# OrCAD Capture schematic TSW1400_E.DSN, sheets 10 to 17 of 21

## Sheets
10 Bank 3: size B; title: Bank3
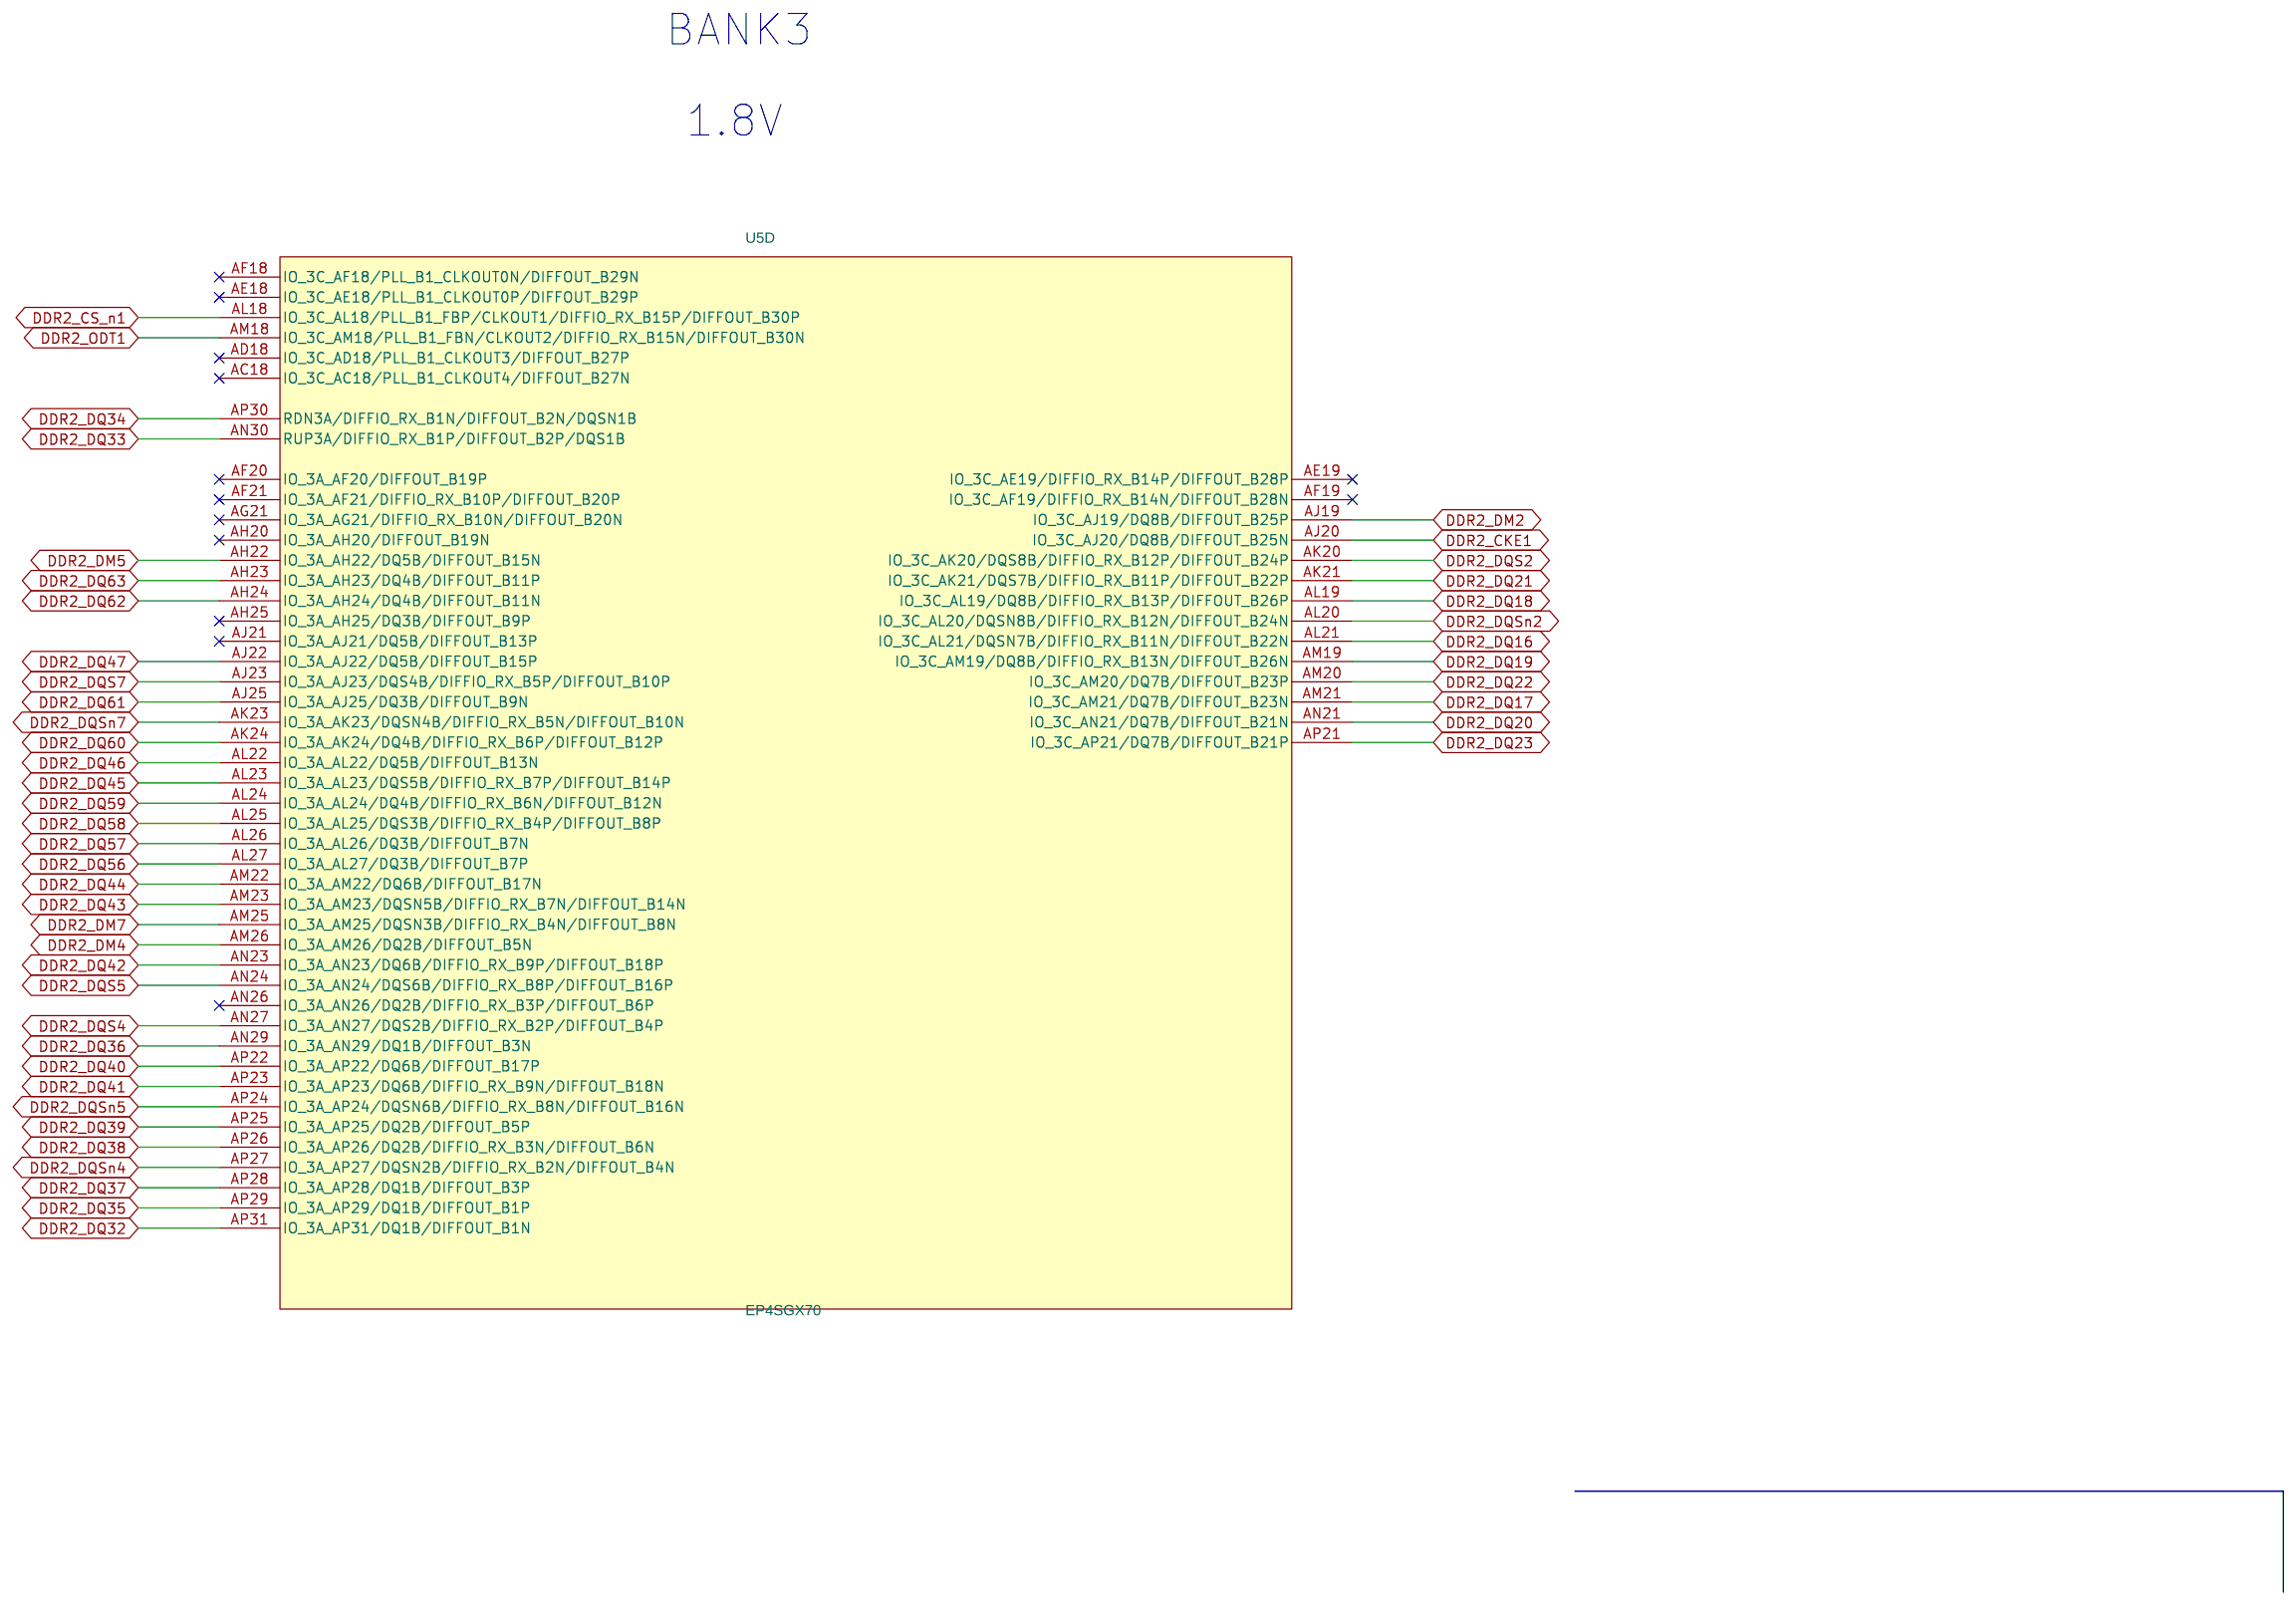
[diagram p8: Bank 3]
11 Bank4: size B; title: Bank4
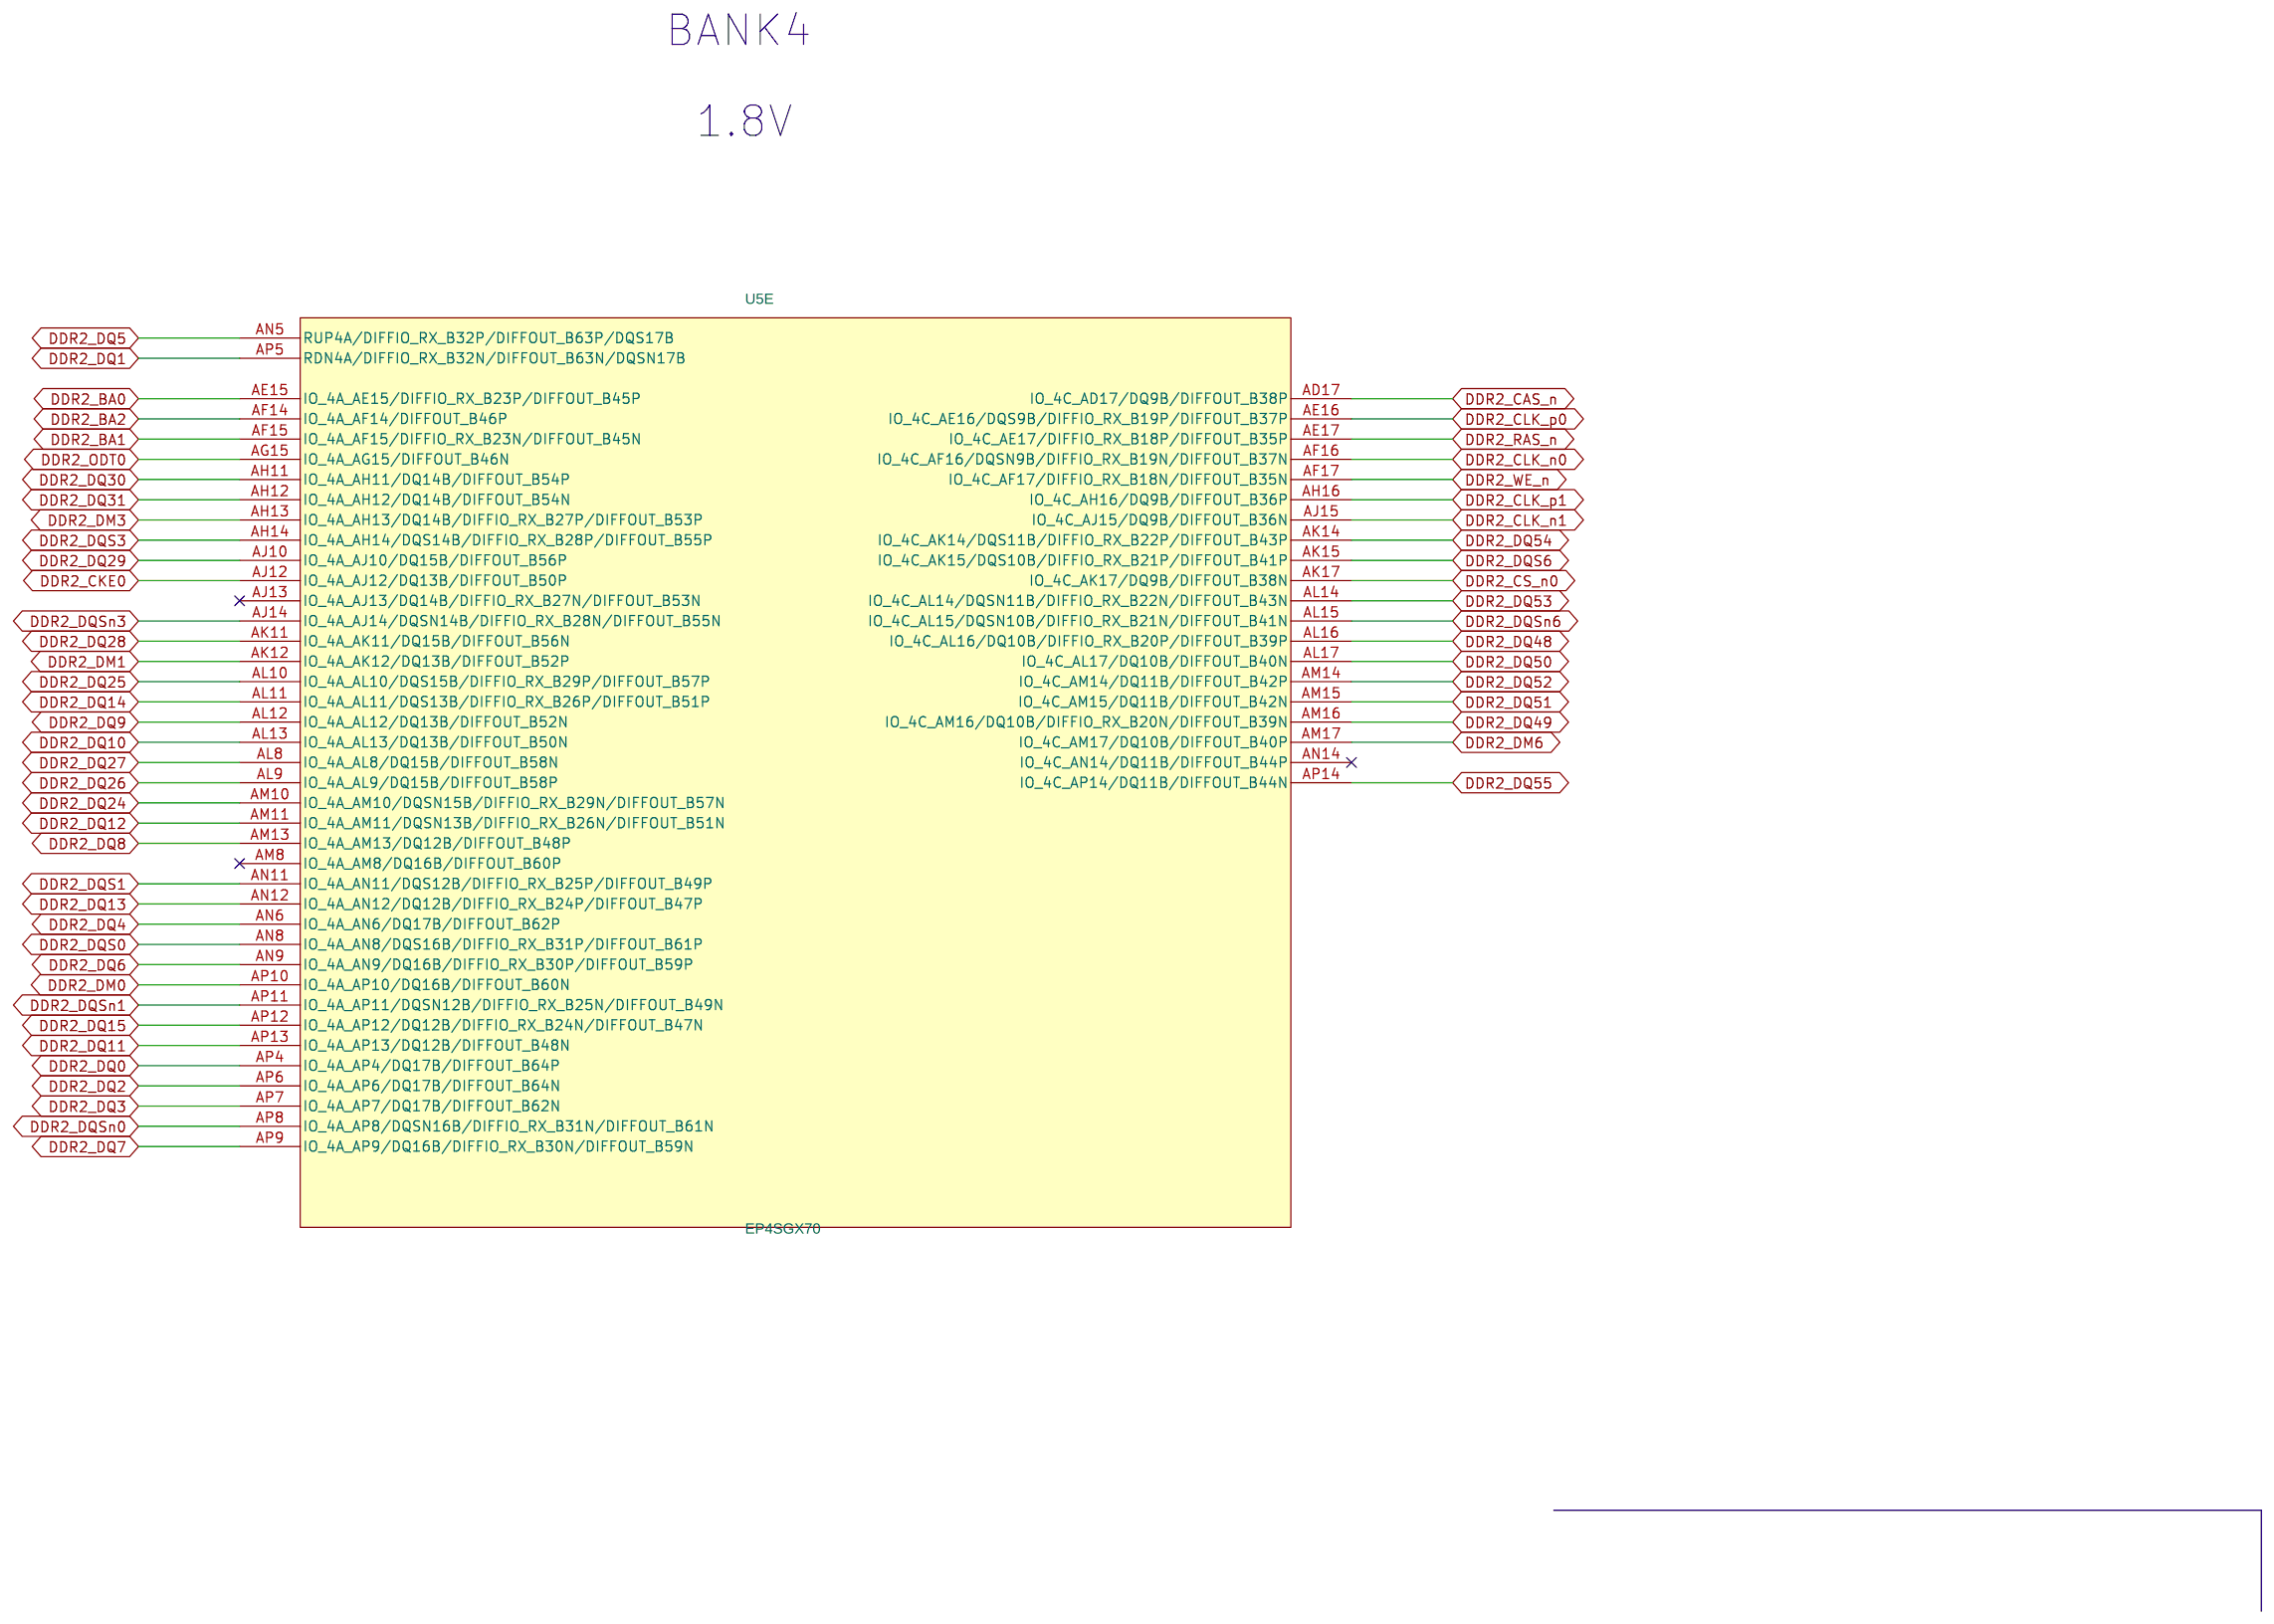
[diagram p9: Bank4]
12 Bank5: size B; title: Bank5
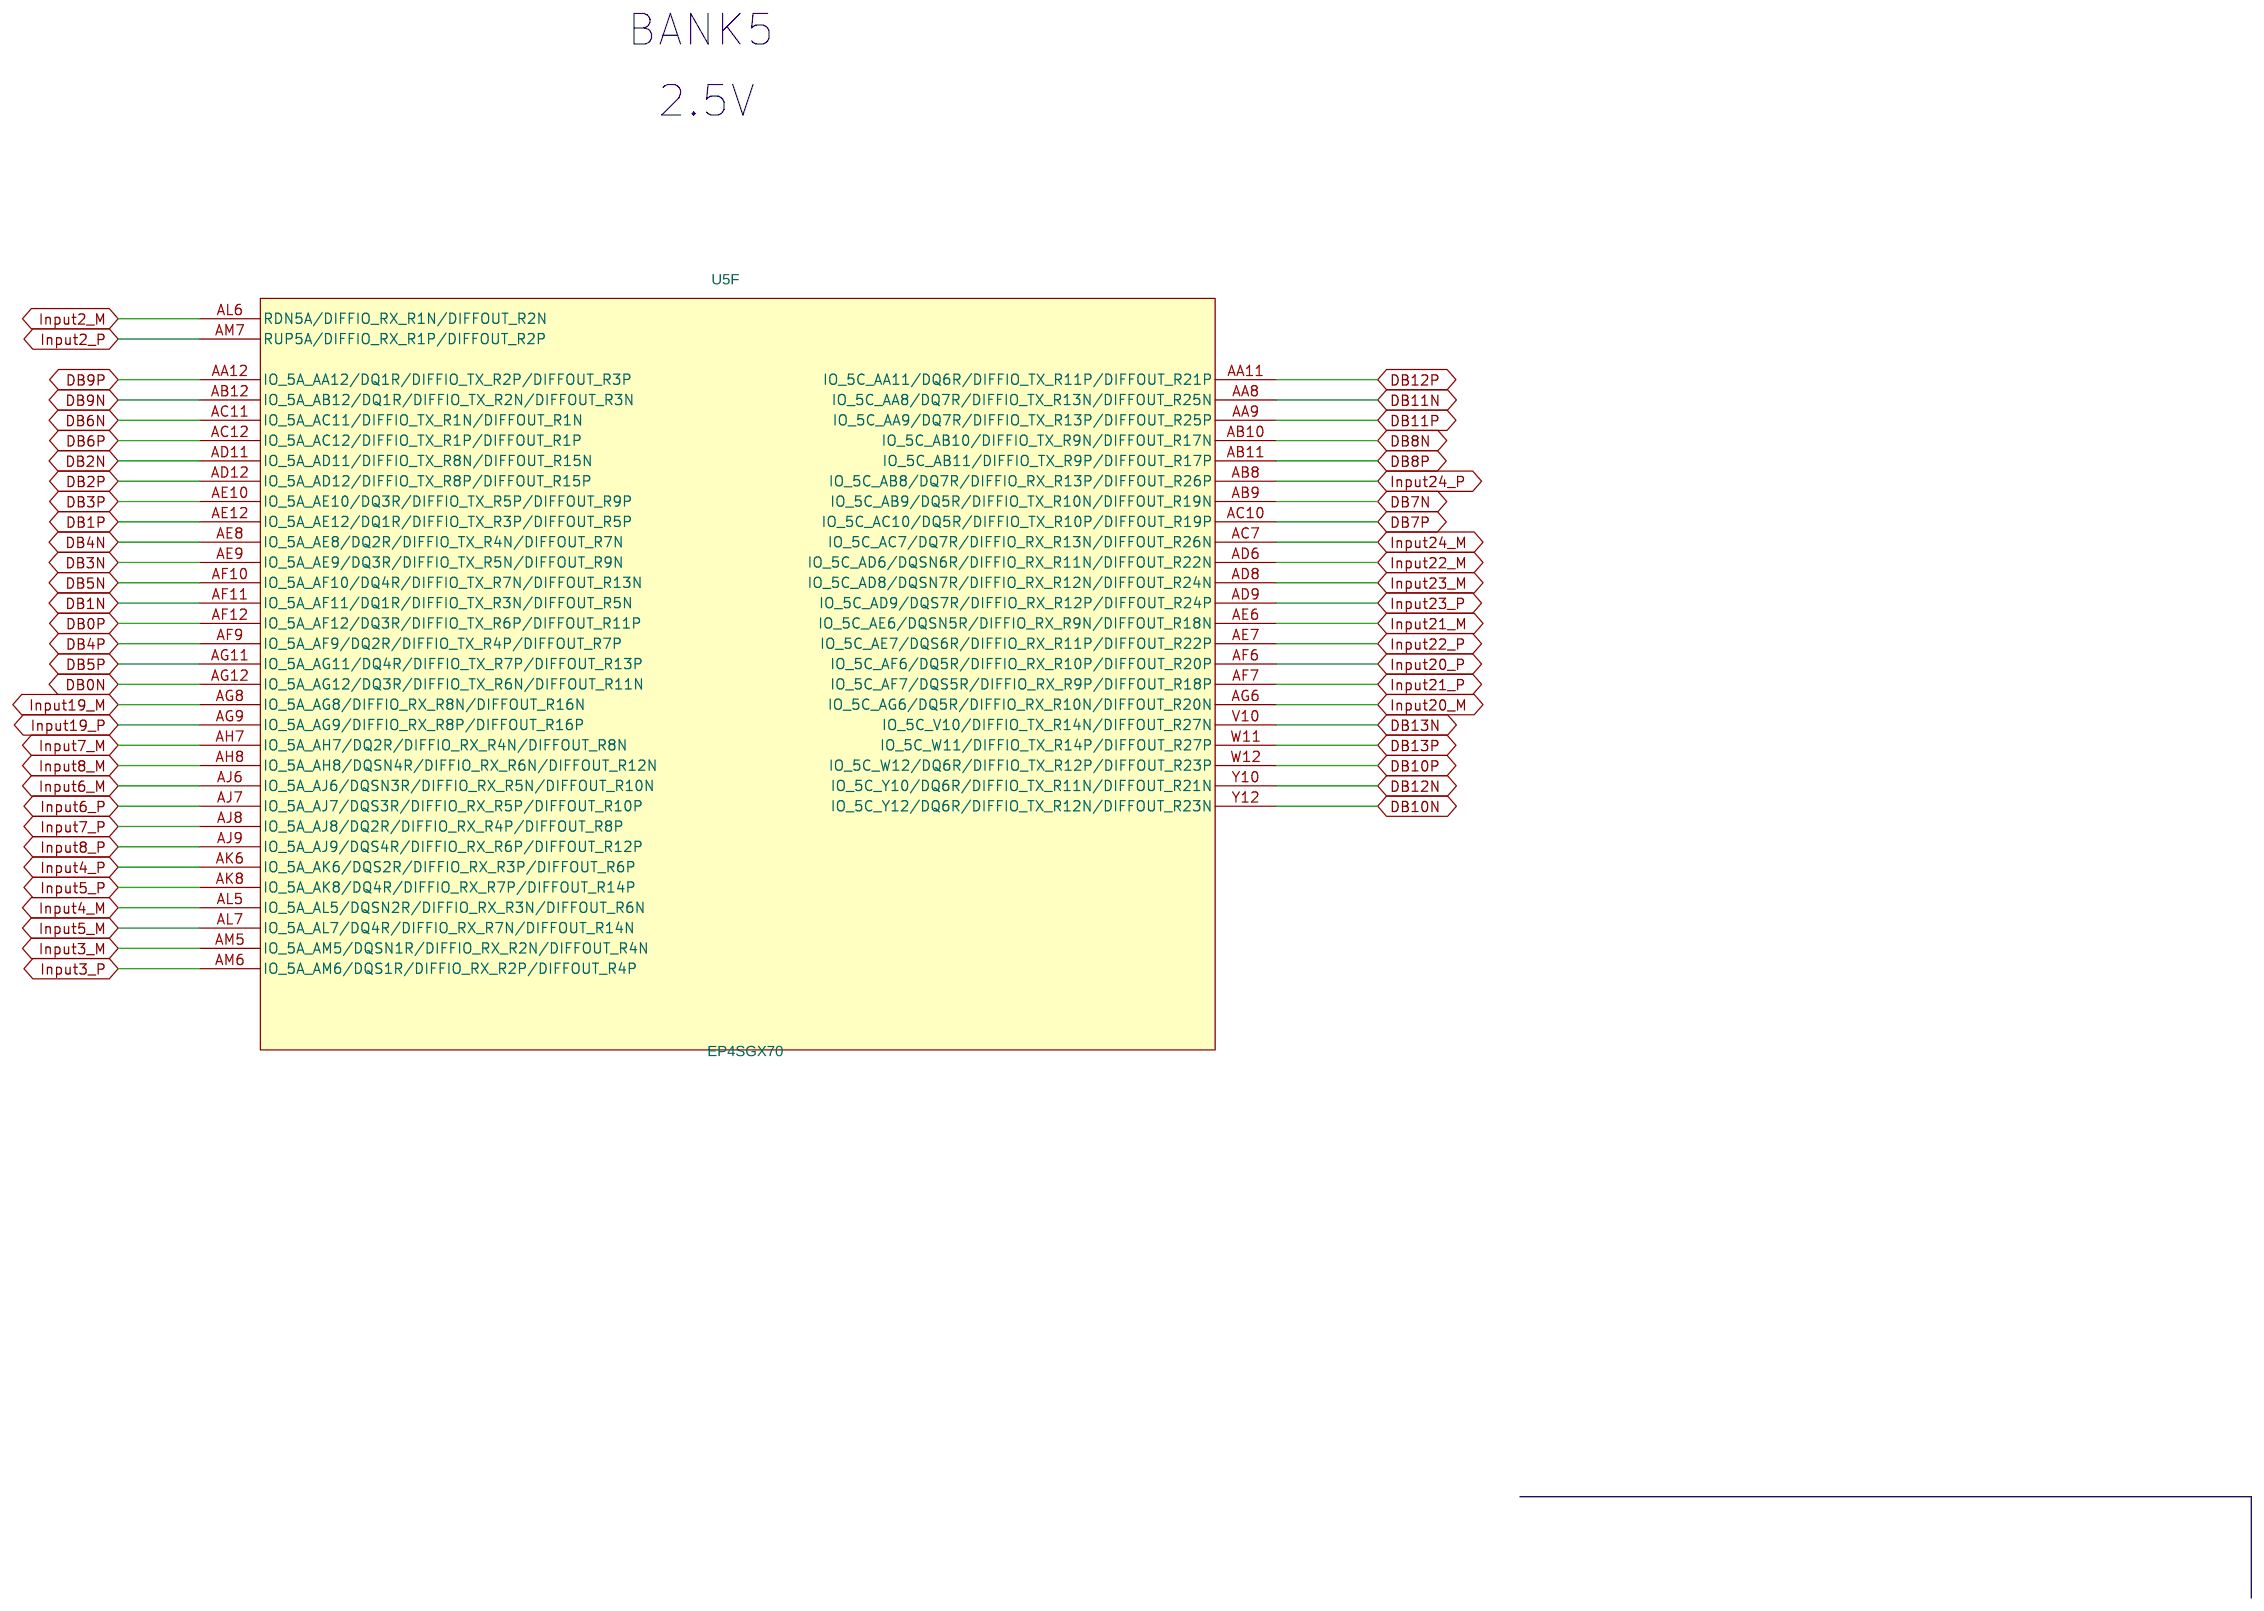
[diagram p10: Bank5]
13 Bank6: size B; title: Bank6
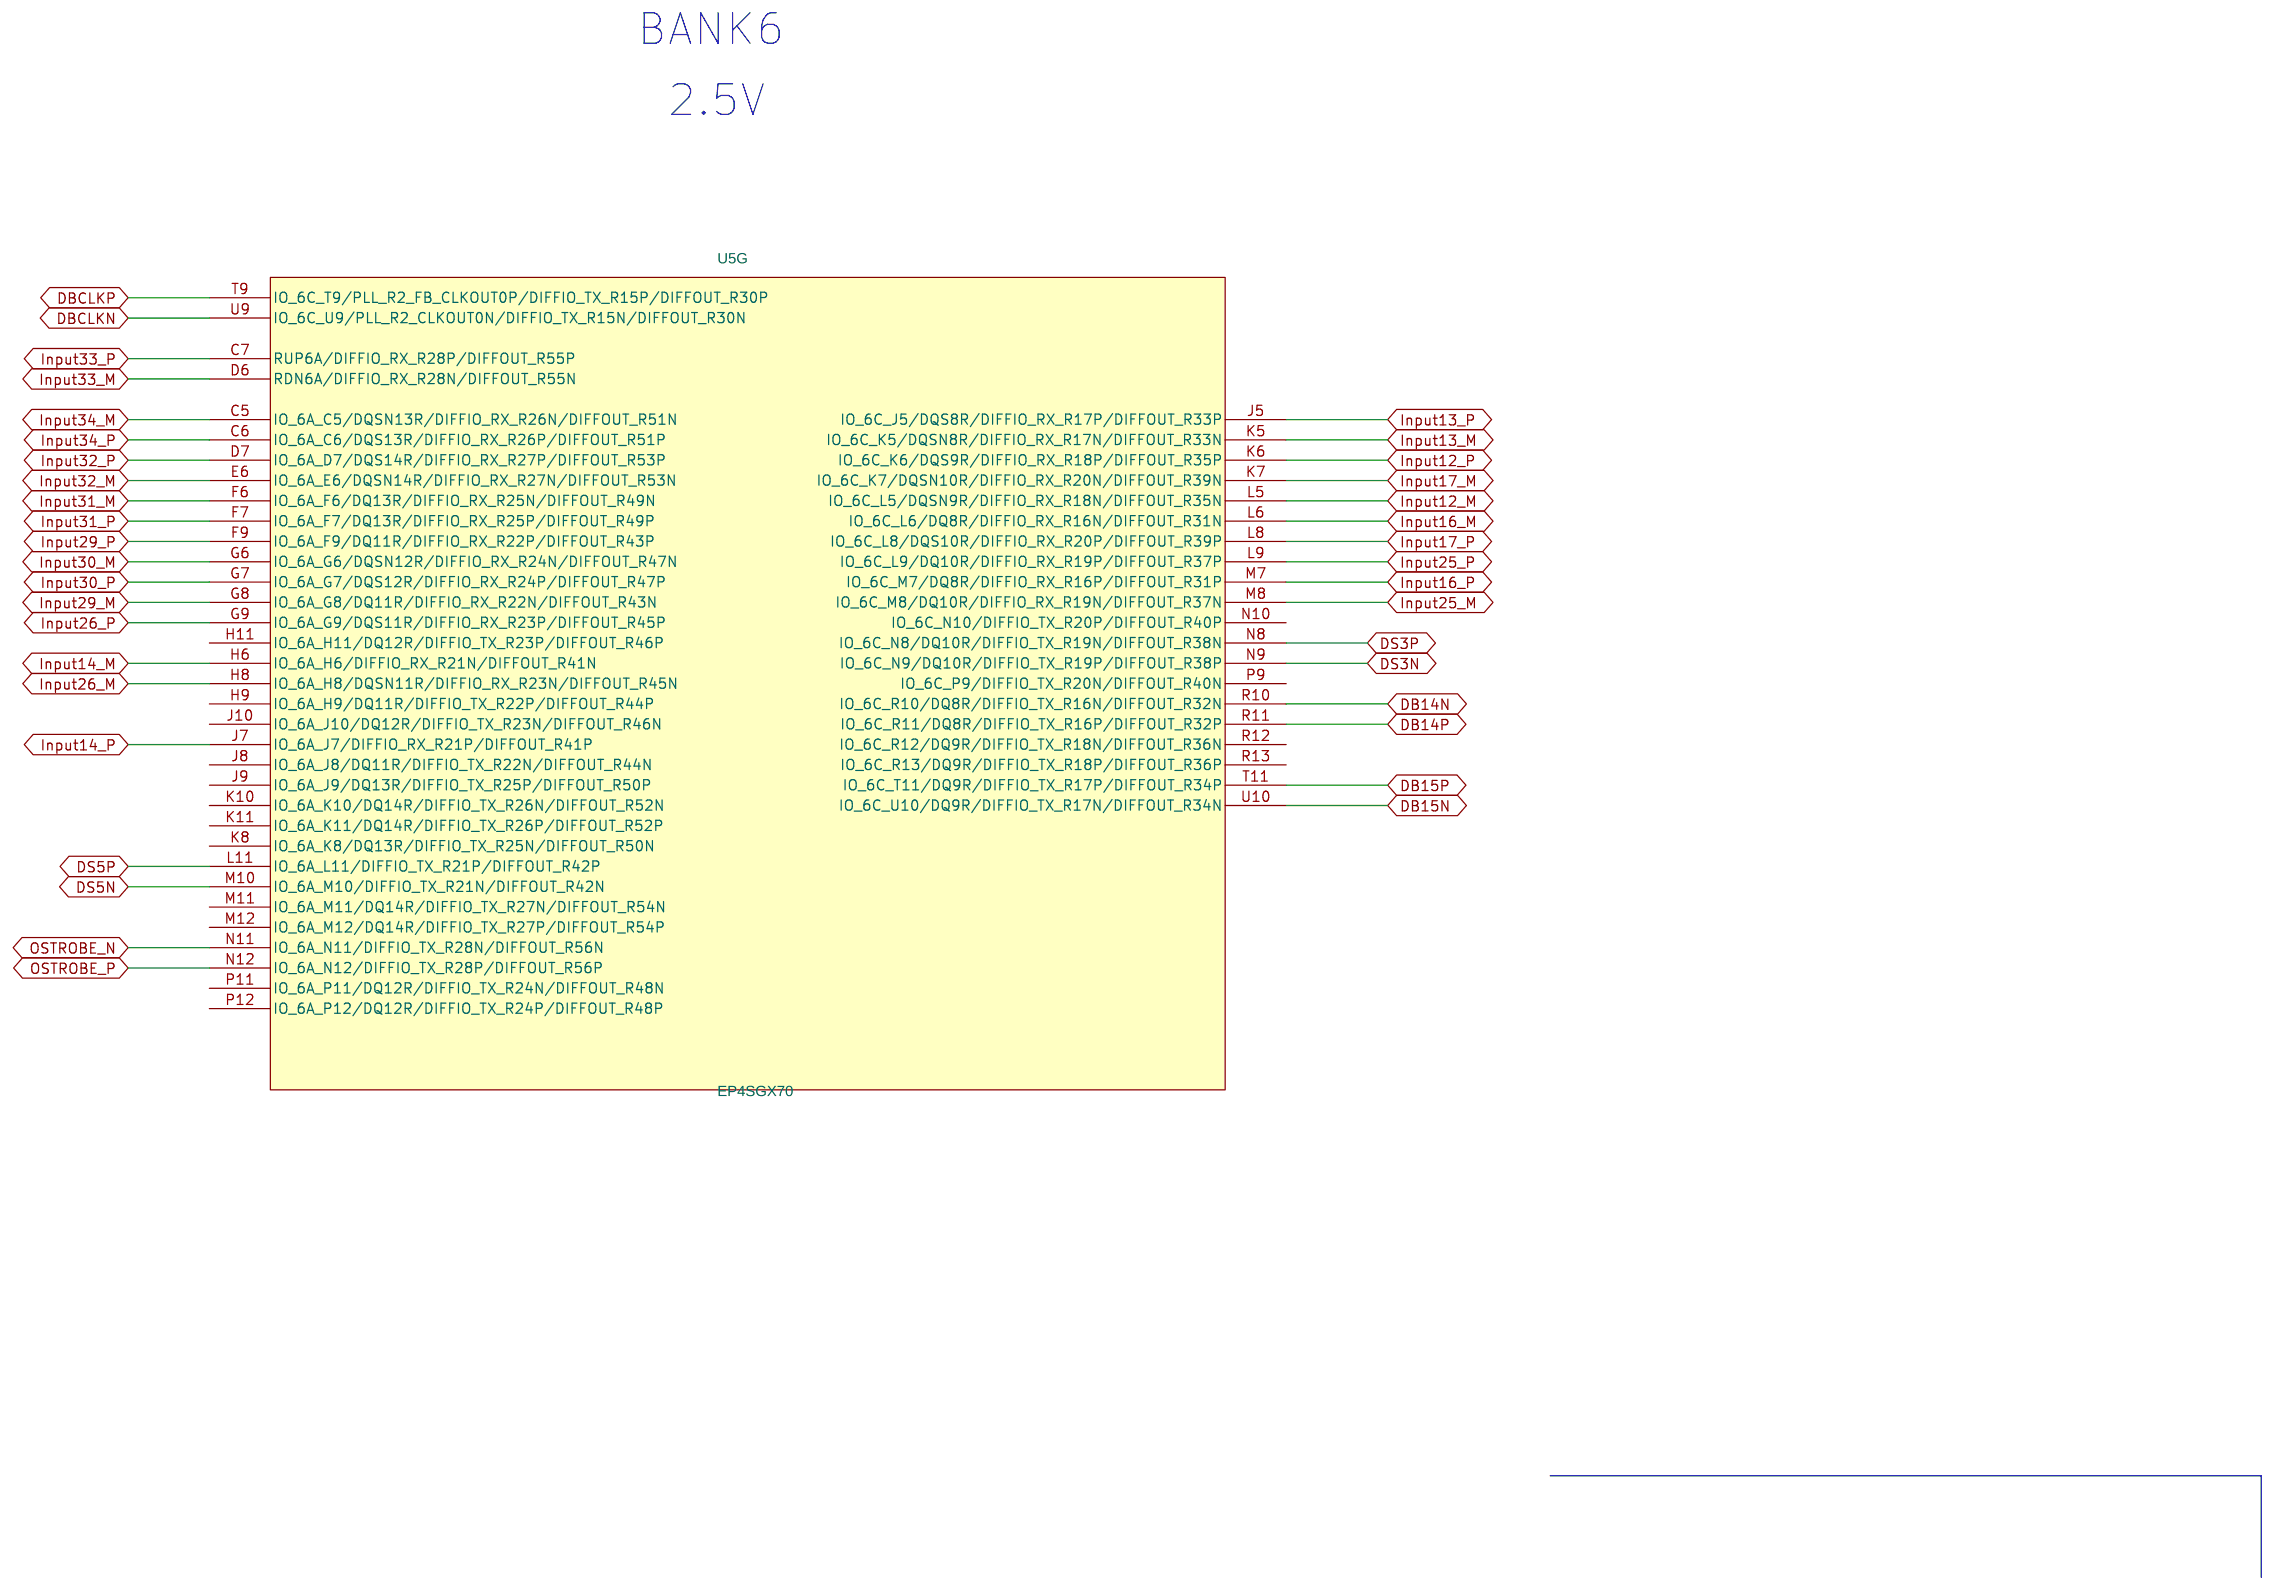
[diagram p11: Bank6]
14 Bank7: size B; title: Bank7
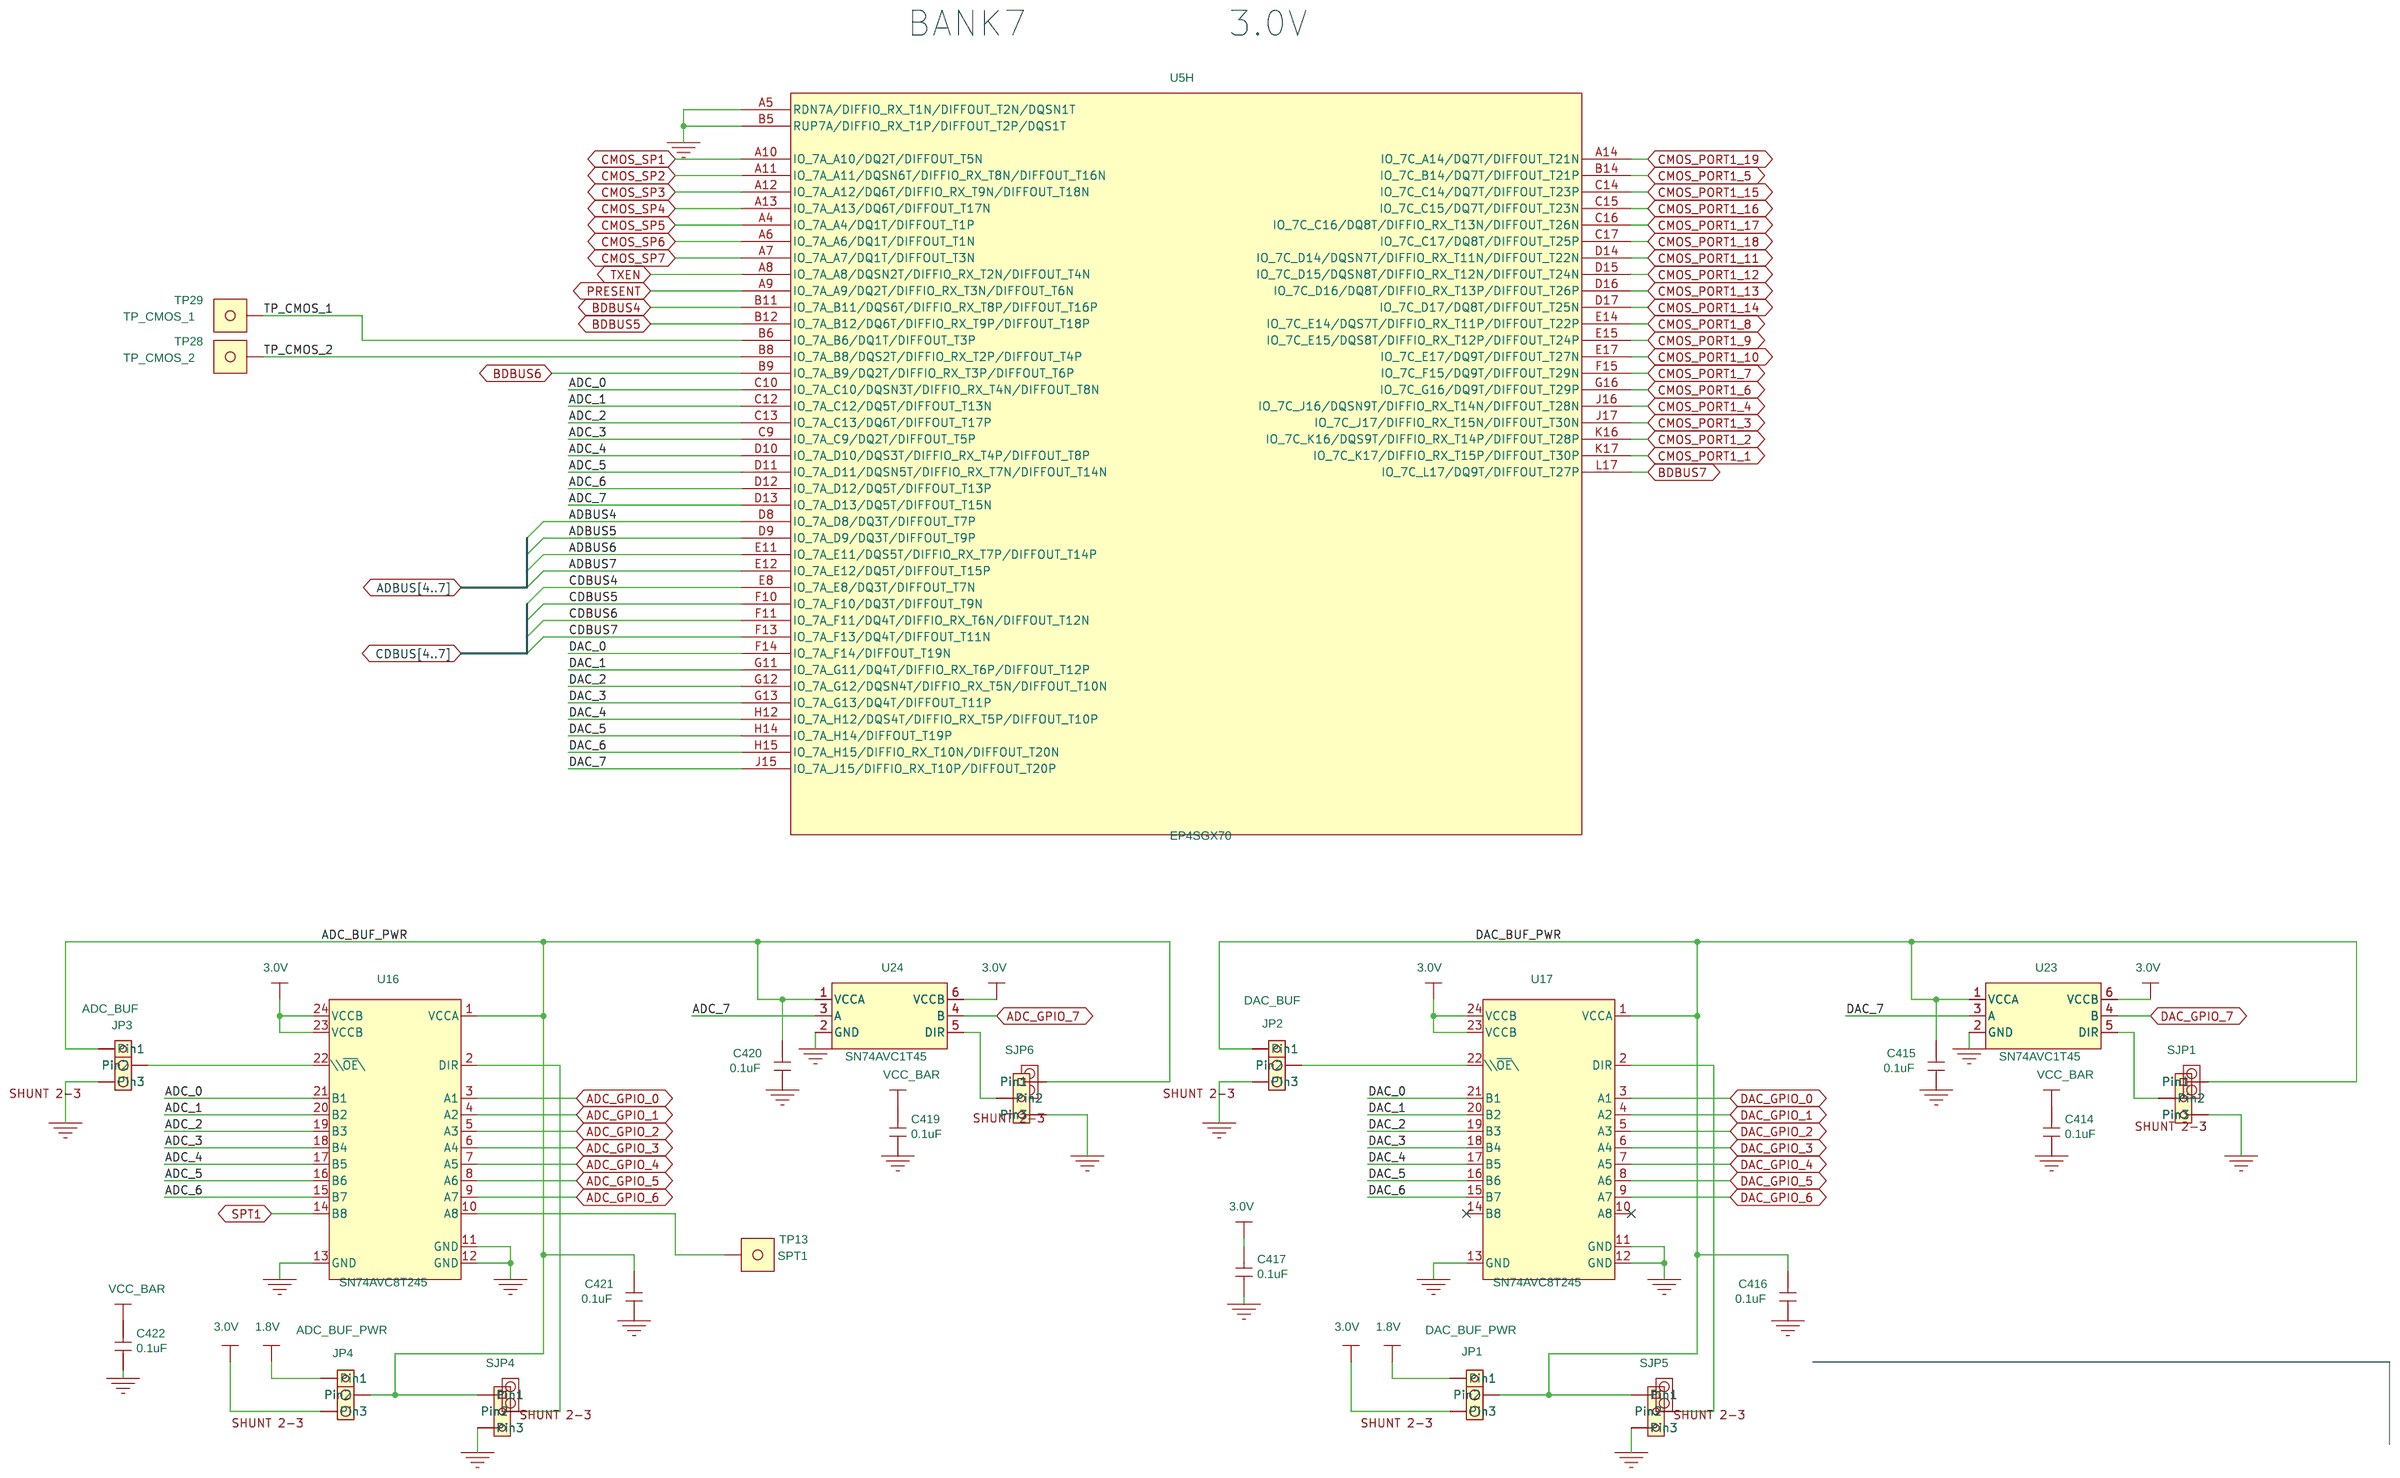
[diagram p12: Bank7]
15 Bank8: size B; title: Bank8
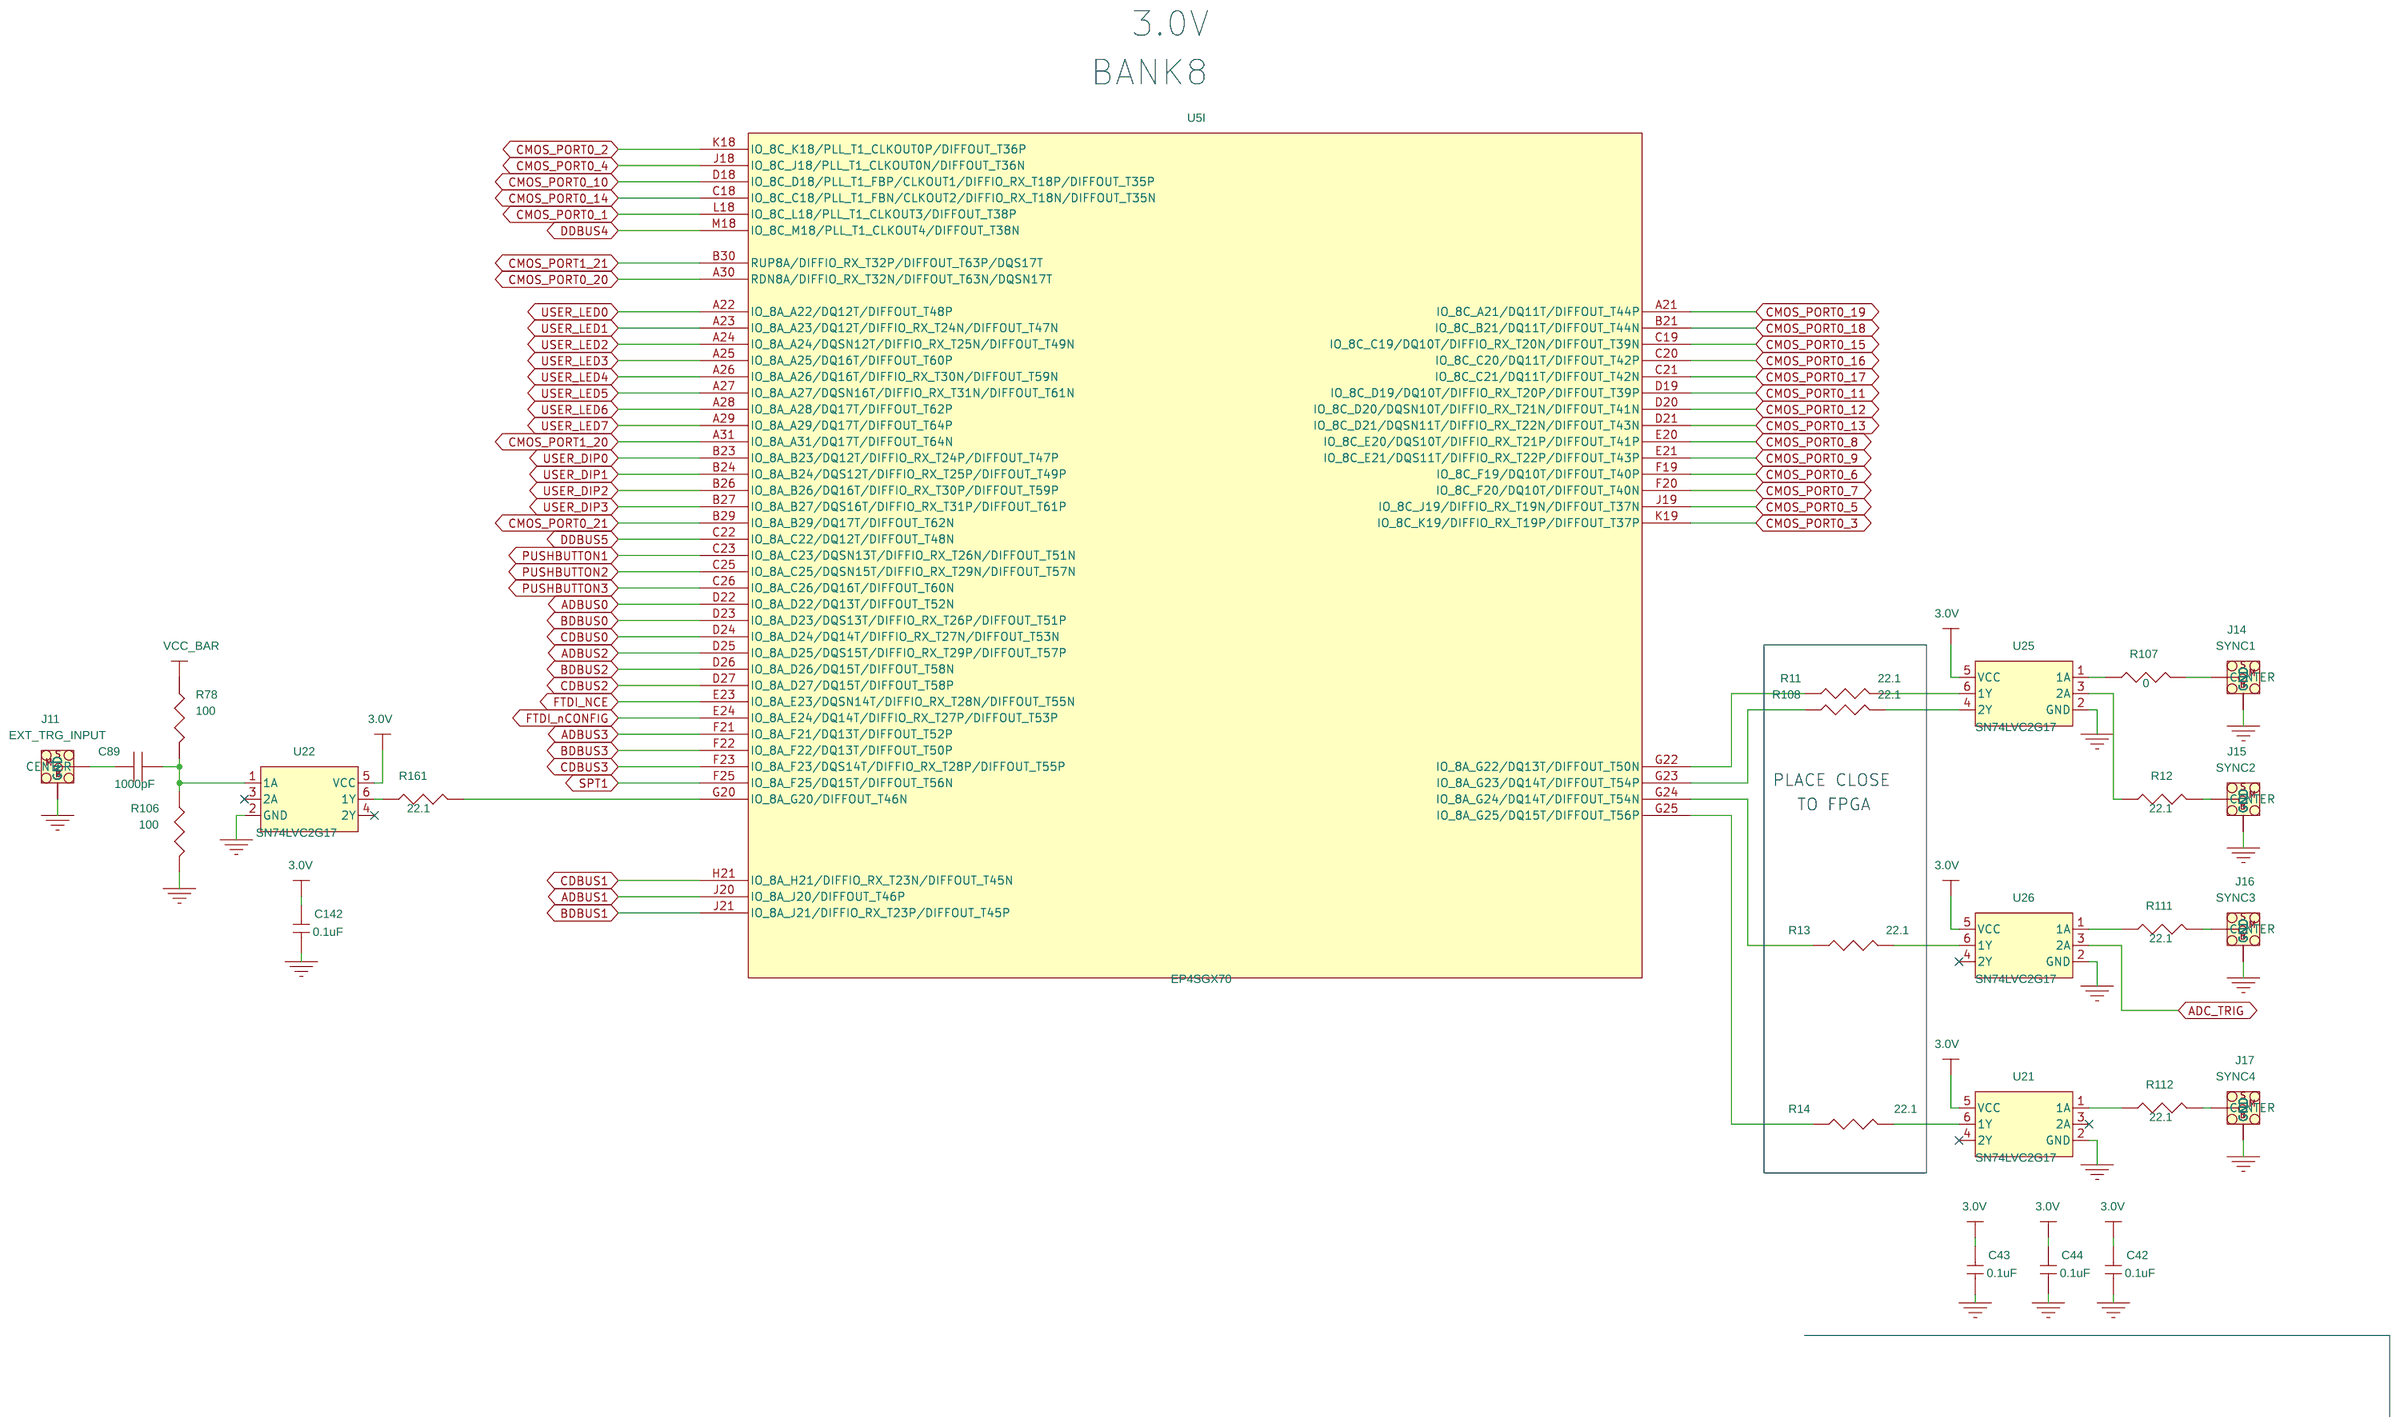
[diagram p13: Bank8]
16 FPGA 0.9V, 1.1V, 1.5V, 1.8: size B; title: POWERS 0.9V, 1.1V, 1.5V, 1.8V
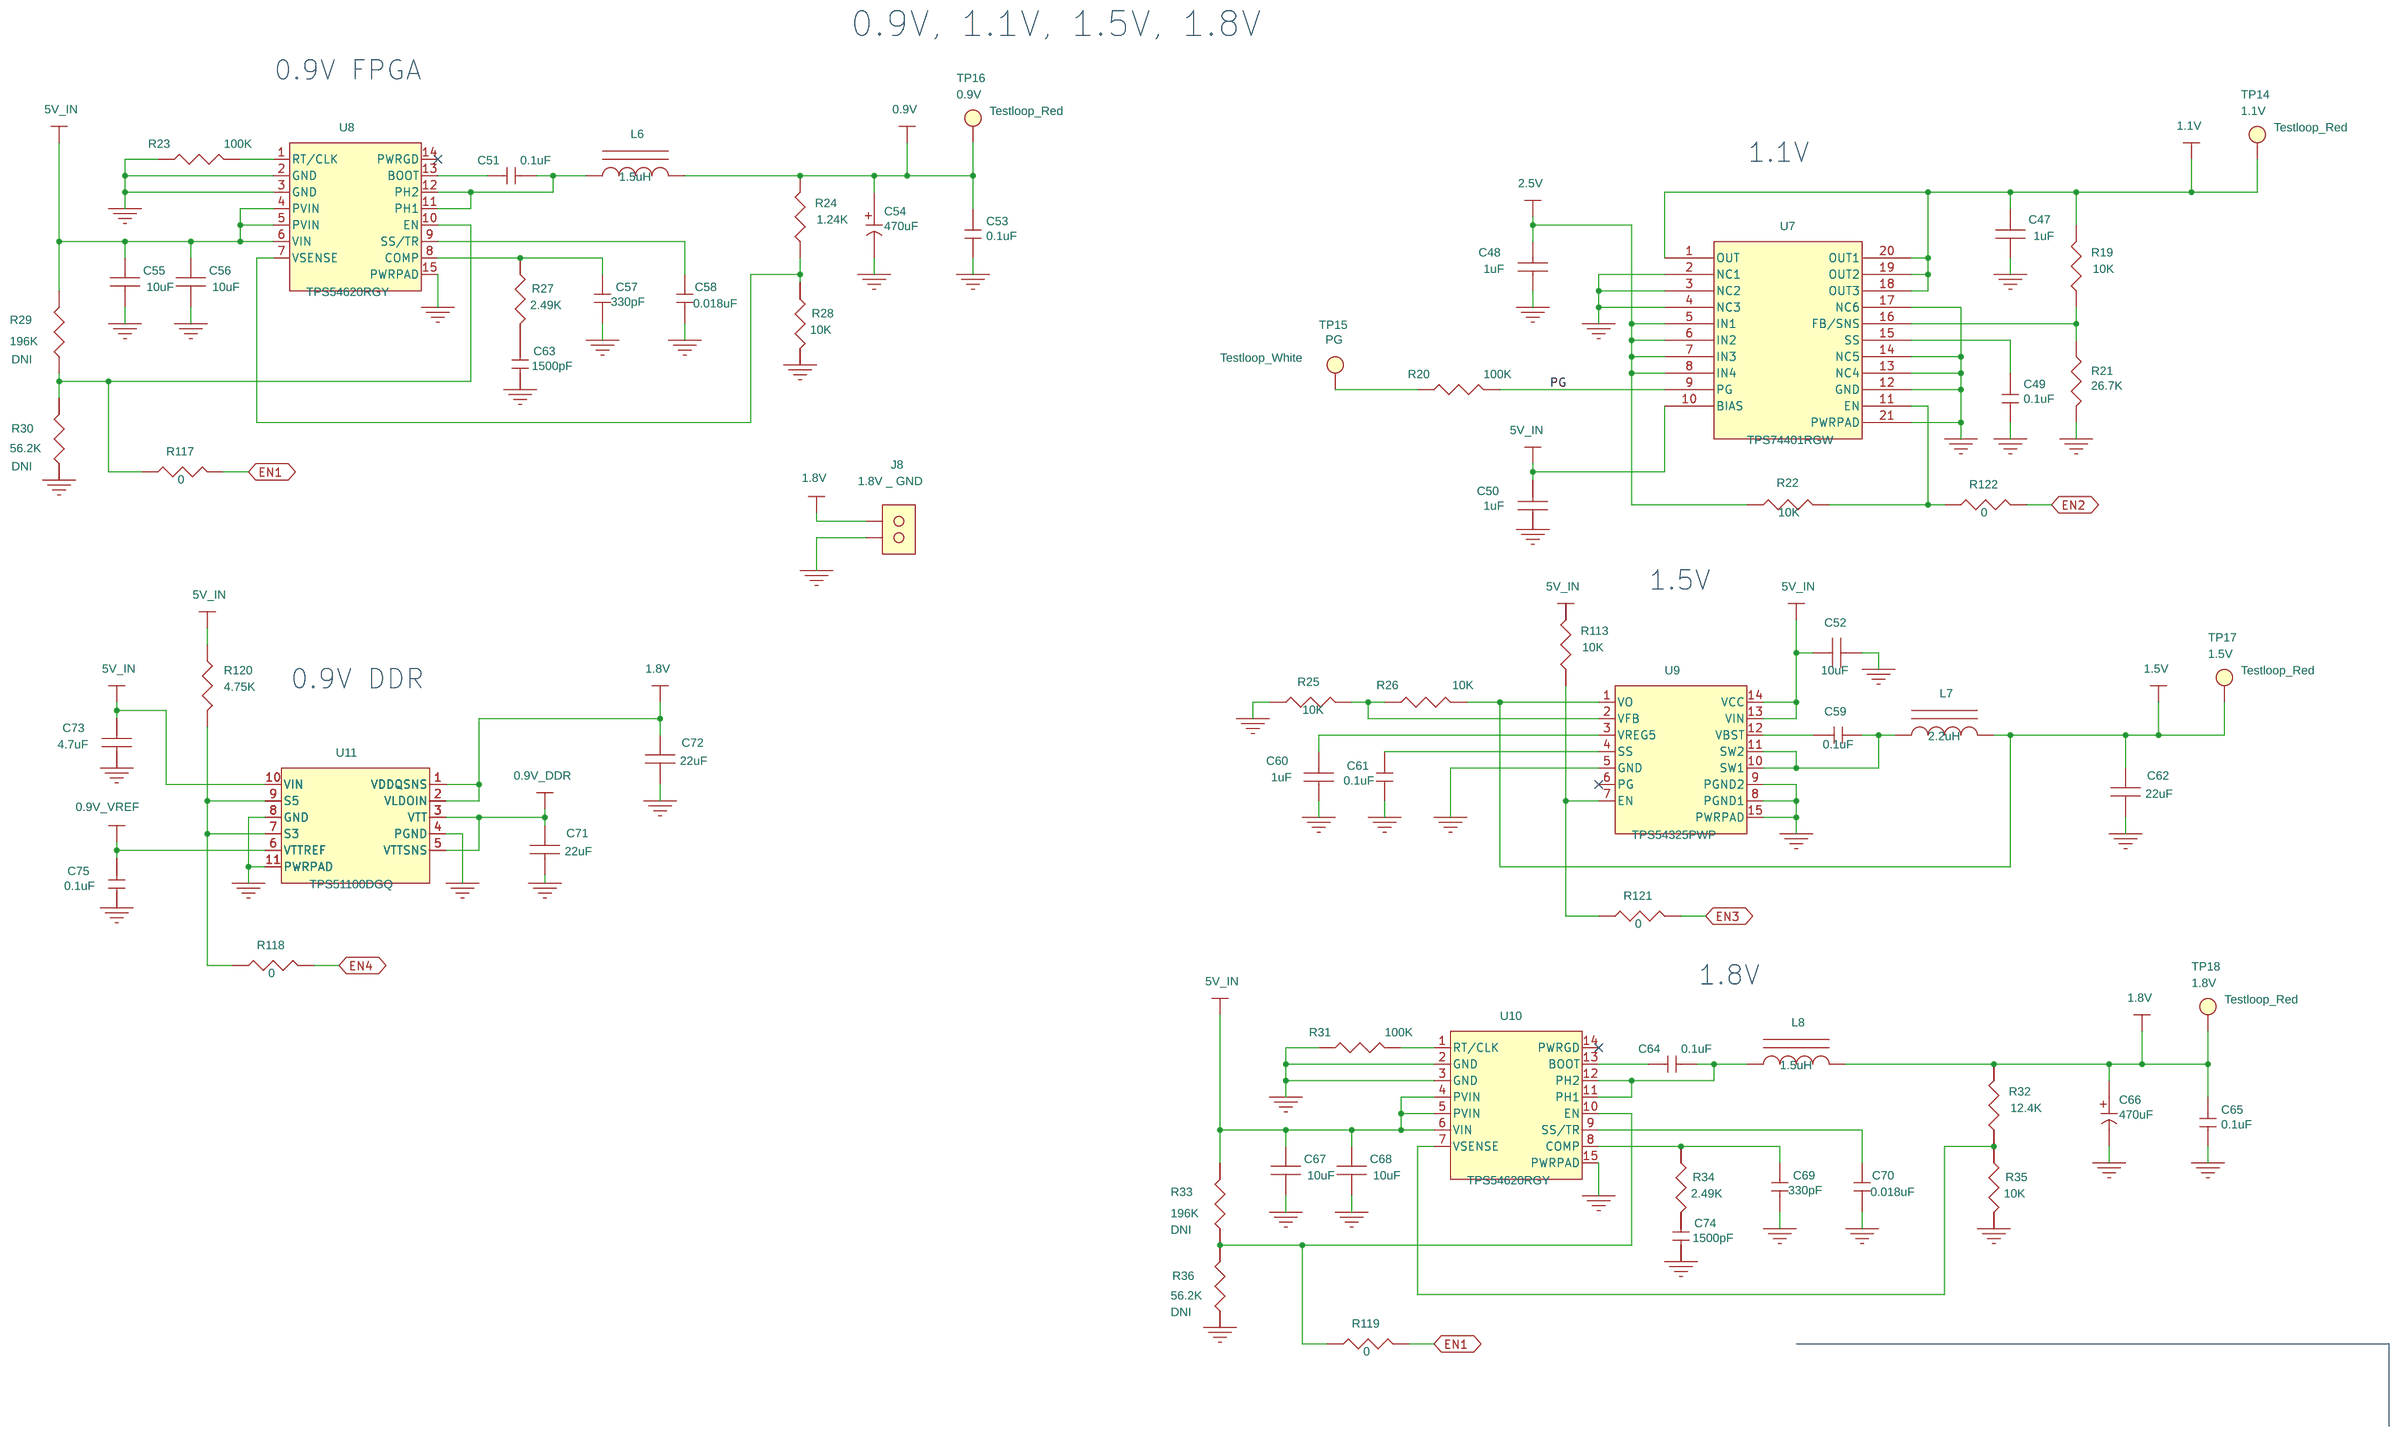
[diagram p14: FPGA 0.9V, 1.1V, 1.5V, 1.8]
17 FPGA 2.5V, 3.0V, 3.3V, 5V: size B; title: POWERS 2.5V, 3.0V, 3.3V, 5V
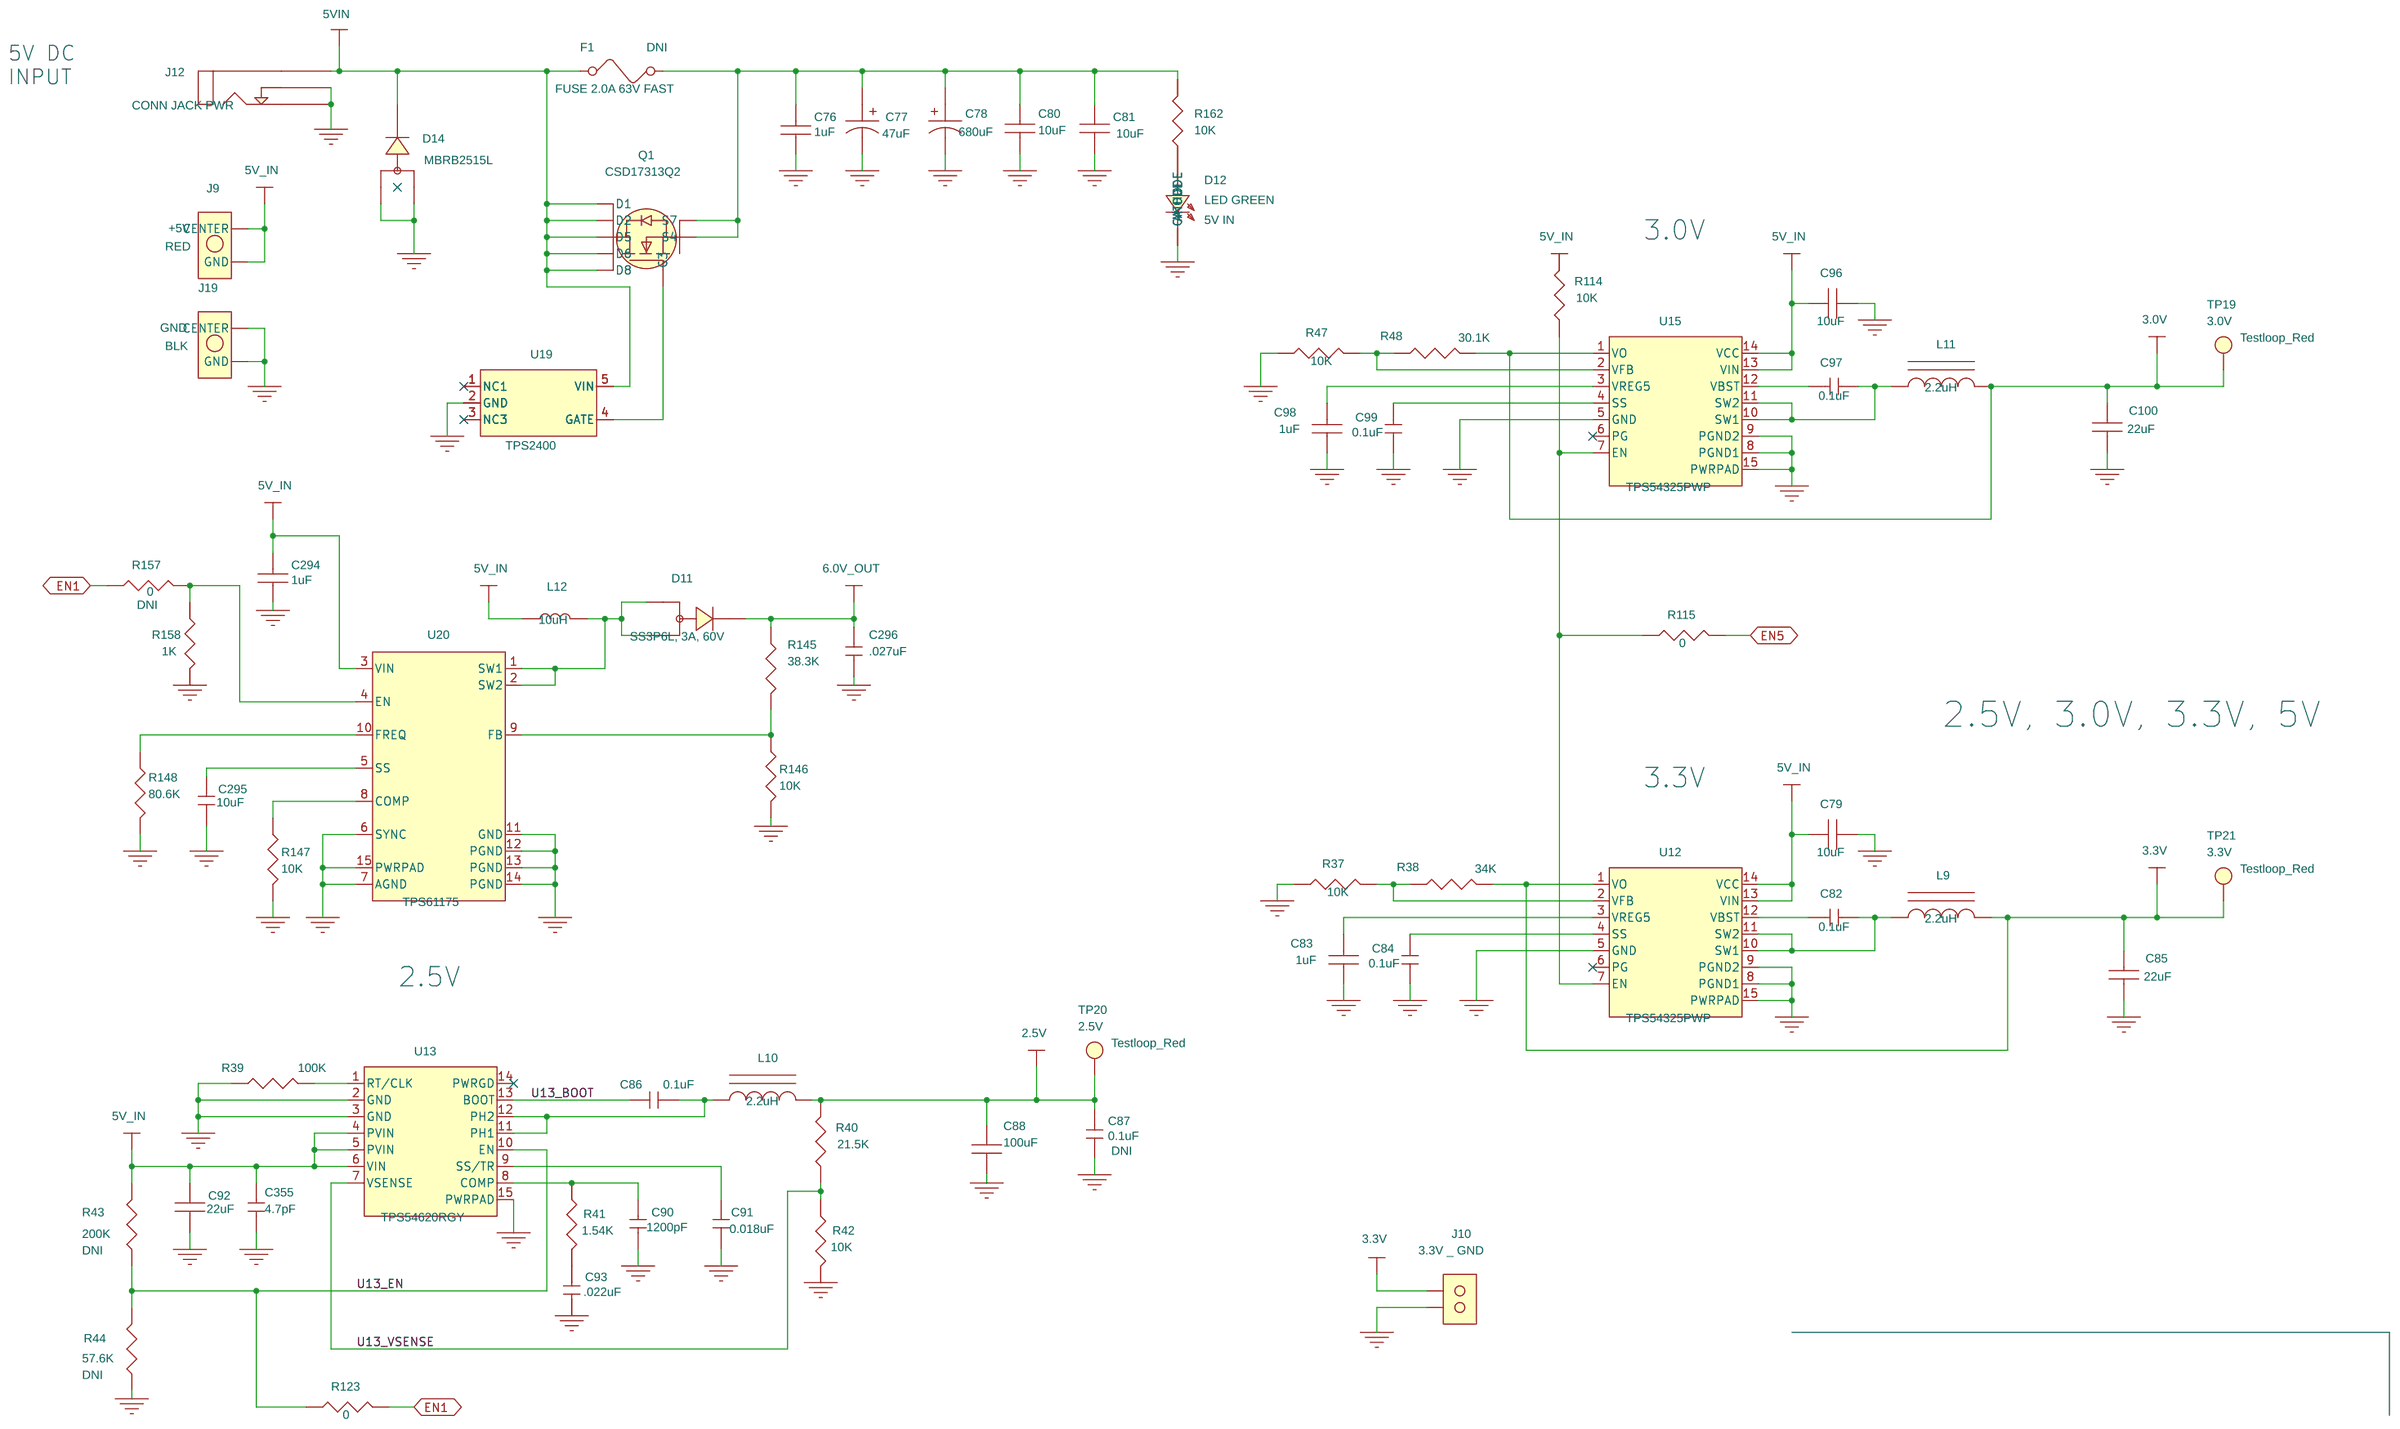
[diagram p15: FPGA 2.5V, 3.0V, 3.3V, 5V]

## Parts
sheet Bank7
C414  0.1uF  [0402]
C415  0.1uF  [0402]
C416  0.1uF  [0402]
C417  0.1uF  [0402]
C419  0.1uF  [0402]
C420  0.1uF  [0402]
C421  0.1uF  [0402]
C422  0.1uF  [0402]
JP1  HDR, THVT, 2POS  [HDR_THVT_1x3_100_M]
JP2  HDR, THVT, 2POS  [HDR_THVT_1x3_100_M]
JP3  HDR, THVT, 2POS  [HDR_THVT_1x3_100_M]
JP4  HDR, THVT, 2POS  [HDR_THVT_1x3_100_M]
SJP1  SOLDER JUMPER, 0603  [JUMPER_SMT_L_0603]
SJP4  SOLDER JUMPER, 0603  [JUMPER_SMT_L_0603]
SJP5  SOLDER JUMPER, 0603  [JUMPER_SMT_L_0603]
SJP6  SOLDER JUMPER, 0603  [JUMPER_SMT_L_0603]
TP13  HDR, THVT, 1POS  [HDR_THVT_1x1]
TP28  HDR, THVT, 1POS  [HDR_THVT_1x1]
TP29  HDR, THVT, 1POS  [HDR_THVT_1x1]
U16  SN74AVC8T245  [TVSOP_24_201X177_16]
U17  SN74AVC8T245  [TVSOP_24_201X177_16]
U23  SN74AVC1T45  [SOT_6_120X69_37]
U24  SN74AVC1T45  [SOT_6_120X69_37]
Z_SH-H37  SHUNT-HEADER
Z_SH-H40  SHUNT-HEADER
Z_SH-H42  SHUNT-HEADER
Z_SH-H43  SHUNT-HEADER
Z_SH-J5  SHUNT-JUMPER-0603
Z_SH-J8  SHUNT-JUMPER-0603
Z_SH-J9  SHUNT-JUMPER-0603
Z_SH-J10  SHUNT-JUMPER-0603
sheet Bank8
C42  0.1uF  [0402]
C43  0.1uF  [0402]
C44  0.1uF  [0402]
C89  1000pF  [0402]
C142  0.1uF  [0402]
J11  SMB_THVT_REC  [SMA_THVT_312x312]
J14  SMB_THVT_REC  [SMA_THVT_312x312]
J15  SMB_THVT_REC  [SMA_THVT_312x312]
J16  SMB_THVT_REC  [SMA_THVT_312x312]
J17  SMB_THVT_REC  [SMA_THVT_312x312]
R11  22.1  [0402]
R12  22.1  [0402]
R13  22.1  [0402]
R14  22.1  [0402]
R78  100  [0402]
R106  100  [0402]
R107  0  [0402]
R108  22.1  [0402]
R111  22.1  [0402]
R112  22.1  [0402]
R161  22.1  [0402]
U21  SN74LVC2G17  [SC70_6_85X55_0P65MM]
U22  SN74LVC2G17  [SC70_6_85X55_0P65MM]
U25  SN74LVC2G17  [SC70_6_85X55_0P65MM]
U26  SN74LVC2G17  [SC70_6_85X55_0P65MM]
sheet Bank 2
U5  EP4SGX70  [BGA_1152_39]  (sections A,B,C,D,E,F,G,H,I,J,K,L,M,N)
sheet FPGA 0.9V, 1.1V, 1.5V, 1.8
C47  1uF  [0603]
C48  1uF  [0603]
C49  0.1uF  [0603]
C50  1uF  [0603]
C51  0.1uF  [0603]
C52  10uF  [0603]
C53  0.1uF  [0603]
C54  470uF  [TANT_E]
C55  10uF  [0603]
C56  10uF  [0603]
C57  330pF  [0603]
C58  0.018uF  [0603]
C59  0.1uF  [0603]
C60  1uF  [0603]
C61  0.1uF  [0603]
C62  22uF  [0603]
C63  1500pF  [0603]
C64  0.1uF  [0603]
C65  0.1uF  [0603]
C66  470uF  [TANT_E]
C67  10uF  [0603]
C68  10uF  [0603]
C69  330pF  [0603]
C70  0.018uF  [0603]
C71  22uF  [0603]
C72  22uF  [0603]
C73  4.7uF  [0603]
C74  1500pF  [0603]
C75  0.1uF  [0603]
J8  HMTSW-102-07-G-S-.240  [HDR_THVT_1x2_100_M]
L6  1.5uH  [IND_SM_MSS1048]
L7  2.2uH  [IND_SM_7447789002]
L8  1.5uH  [IND_SM_MSS1048]
R19  10K  [0603]
R20  100K  [0603]
R21  26.7K  [0603]
R22  10K  [0603]
R23  100K  [0603]
R24  1.24K  [0603]
R25  10K  [0603]
R26  10K  [0603]
R27  2.49K  [0603]
R28  10K  [0603]
R29  196K  [0603]
R30  56.2K  [0603]
R31  100K  [0603]
R32  12.4K  [0603]
R33  196K  [0603]
R34  2.49K  [0603]
R35  10K  [0603]
R36  56.2K  [0603]
R113  10K  [0603]
R117  0  [0603]
R118  0  [0603]
R119  0  [0603]
R120  4.75K  [0603]
R121  0  [0603]
R122  0  [0603]
TP14  Testloop_Red  [TP_THVT_060_RND]
TP15  Testloop_White  [TP_THVT_060_RND]
TP16  Testloop_Red  [TP_THVT_060_RND]
TP17  Testloop_Red  [TP_THVT_060_RND]
TP18  Testloop_Red  [TP_THVT_060_RND]
U7  TPS74401RGW  [QFN_20_203x203_26_pwrpad]
U8  TPS54620RGY  [QFN_14_144x144_pwrpad]
U9  TPS54325PWP  [HTSSOP_14_201x177_26_pwrpad]
U10  TPS54620RGY  [QFN_14_144x144_pwrpad]
U11  TPS51100DGQ  [SOIC_10_122x122_50_pwrpad]
sheet FPGA 2.5V, 3.0V, 3.3V, 5V
C76  1uF  [0603]
C77  47uF  [CAP_SMD_8MM]
C78  680uF  [CAP_SMD_12_5MM]
C79  10uF  [0603]
C80  10uF  [1210]
C81  10uF  [1210]
C82  0.1uF  [0603]
C83  1uF  [0603]
C84  0.1uF  [0603]
C85  22uF  [0603]
C86  0.1uF  [0603]
C87  0.1uF  [0603]
C88  100uF  [1210]
C90  1200pF  [0603]
C91  0.018uF  [0603]
C92  22uF  [0603]
C93  .022uF  [0603]
C96  10uF  [0603]
C97  0.1uF  [0603]
C98  1uF  [0603]
C99  0.1uF  [0603]
C100  22uF  [0603]
C294  1uF  [0603]
C295  10uF  [0603]
C296  .027uF  [0603]
C355  4.7pF  [0603]
D11  SS3P6L, 3A, 60V  [DIODE_SM_SS3P6L]
D12  LED GREEN  [LED_1206]
D14  MBRB2515L  [DIODE_MBRB2515L]
F1  FUSE 2.0A 63V FAST  [1206]
J9  RED  [JACK_THRT_BANANA_2PIN]
J10  HMTSW-102-07-G-S-.240  [HDR_THVT_1x2_100_M]
J12  CONN JACK PWR  [CON_RAPC722_JACK_THVT_3]
J19  BLK  [JACK_THRT_BANANA_2PIN]
L9  2.2uH  [IND_SM_7447789002]
L10  2.2uH  [IND_SM_7447789002]
L11  2.2uH  [IND_SM_7447789002]
L12  10uH  [IND_SM_MSS1048]
Q1  CSD17313Q2  [mosfet_8_2mmx2mm_0p65]
R37  10K  [0603]
R38  34K  [0603]
R39  100K  [0603]
R40  21.5K  [0603]
R41  1.54K  [0603]
R42  10K  [0603]
R43  200K  [0603]
R44  57.6K  [0603]
R47  10K  [0603]
R48  30.1K  [0603]
R114  10K  [0603]
R115  0  [0603]
R123  0  [0603]
R145  38.3K  [0603]
R146  10K  [0603]
R147  10K  [0603]
R148  80.6K  [0603]
R157  0  [0603]
R158  1K  [0402]
R162  10K  [0603]
TP19  Testloop_Red  [TP_THVT_060_RND]
TP20  Testloop_Red  [TP_THVT_060_RND]
TP21  Testloop_Red  [TP_THVT_060_RND]
U12  TPS54325PWP  [HTSSOP_14_201x177_26_pwrpad]
U13  TPS54620RGY  [QFN_14_144x144_pwrpad]
U15  TPS54325PWP  [HTSSOP_14_201x177_26_pwrpad]
U19  TPS2400  [DBV5]
U20  TPS61175  [HTSSOP_14_201X177_26_PWRPAD]

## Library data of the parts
C414-C417 C419-C422 = CAP0603: Mfr_Name: Murata; Mfr_Part_Number: GRM155R71C104KA88D; TOL: 10%; Voltage: 16V
JP1 = JUMPER_1x3_100: Mfr_Name: SAMTEC; Mfr_Part_Number: HTSW-103-07-G-S; TI_Silktext: DAC_BUF_PWR
JP2 = JUMPER_1x3_100: Mfr_Name: SAMTEC; Mfr_Part_Number: HTSW-103-07-G-S; TI_Silktext: DAC_BUF
JP3 = JUMPER_1x3_100: Mfr_Name: SAMTEC; Mfr_Part_Number: HTSW-103-07-G-S; TI_Silktext: ADC_BUF
JP4 = JUMPER_1x3_100: Mfr_Name: SAMTEC; Mfr_Part_Number: HTSW-103-07-G-S; TI_Silktext: ADC_BUF_PWR
SJP1 = Jumper_1x3_100_0: Mfr_Name: NO PART; Mfr_Part_Number: DNI; Shunt: SHUNT 2-3; TI_Silktext: <TI_Silktext>
SJP4 SJP5 = JUMPER_SMD_1X3: Mfr_Name: NO PART; Shunt: SHUNT 2-3; TI_Silktext: <TI_Silktext>
SJP6 = Jumper_1x3_100_0: Manufacturer: NO PART; Mfr_Name: NO PART; Mfr_Part_Number: DNI; Shunt: SHUNT 2-3; TI_Silktext: <TI_Silktext>
TP13 = HEADER_1x1: Mfr_Name: SAMTEC; Mfr_Part_Number: HTSW-101-07-G-S; TI_SILKTEXT: SPT1
TP28 = HEADER_1x1: Mfr_Name: SAMTEC; Mfr_Part_Number: HTSW-101-07-G-S; TI_SILKTEXT: TP_CMOS_2
TP29 = HEADER_1x1: Mfr_Name: SAMTEC; Mfr_Part_Number: HTSW-101-07-G-S; TI_SILKTEXT: TP_CMOS_1
U16 U17 = SN74AVC8T245
U23 U24 = SN74AVC1T45: Mfr_Name: Texas Instruments; Mfr_Part_Number: SN74AVC1T45DBVR
Z_SH-H37 Z_SH-H40 Z_SH-H42 Z_SH-H43 = SHUNT-3PINHEADER: TI_SILK: SHUNT 2-3
Z_SH-J5 Z_SH-J8-Z_SH-J10 = SHUNT-JUMPER-0603: Mfr_Name: PANASONIC; Shunt: SHUNT 2-3
C42-C44 C142 = CAP_0402_0.1uF: Mfr_Name: Murata
C89 = CAP_NP_0: Mfr_Name: TAIYO YUDEN; Mfr_Part_Number: TMK105SD102JV-F; TOL: 5%; VOLTAGE: 25V
J11 = SMA-THVT_142-0701-201_REC: TI_Silktext: EXT_TRG_INPUT
J14 = SMA-THVT_142-0701-201_REC: TI_Silktext: SYNC1
J15 = SMA-THVT_142-0701-201_REC: TI_Silktext: SYNC2
J16 = SMA-THVT_142-0701-201_REC: TI_Silktext: SYNC3
J17 = SMA-THVT_142-0701-201_REC: TI_Silktext: SYNC4
R11-R14 R108 R111 R112 R161 = Res_0402_22.1_H
R78 R106 = Res_0402_100
R107 = Res_0402_Zero_H
U21 U22 U25 U26 = SN74LVC2G17
U5 = EP4SGX70F1152_2
C47 C48 C50 C60 C76 C83 C98 C294 = CAP_0603_H: Mfr_Name: Murata; Mfr_Part_Number: GRM188R60J105KA01D; Tolerance: 10%; Voltage: 6.3V
C49 C51 C53 C59 C61 C64 C65 C75 C82 C84 C86 C97 C99 = CAP0603: Mfr_Name: Murata; Mfr_Part_Number: GRM188R71C104KA01D; PART_NUMBER: ECJ-1VB1C104K; TOL: 10%; Voltage: 16V
C52 C55 C56 C67 C68 C79 C96 = CAP: Mfr_Name: Murata; Mfr_Part_Number: GRM188R60J106ME47D; TOL: 20%; VOLTAGE: 6.3V
C54 C66 = CAP_POL-E: Mfr_Name: Kemet; Mfr_Part_Number: B45197A2477K509
C57 C69 = CAP0603: Mfr_Name: Murata; Mfr_Part_Number: GRM188R72A331KA01D
C58 C70 C91 = CAP0603: Mfr_Name: Murata; Mfr_Part_Number: GRM188R71H183KA01D
C62 C71 C72 C85 C100 = CAP_NP: CLASS: DISCRETE; Mfr_Name: Taiyo Yuden; Mfr_Part_Number: AMK107BJ226MA-T; TOL: 20%; VOLTAGE: 4V
C63 C74 = CAP0603: Mfr_Name: Murata; Mfr_Part_Number: GRM188R71H152KA01D
C73 = CAP_NP_0: Mfr_Name: Kemet; Mfr_Part_Number: C0603C475K8PACTU; TOL: 10%; VOLTAGE: 10V
J8 = HEADER_1x2_100: TI_SILKTEXT: 1.8V _ GND
L6 L8 = INDUCTOR-1: Mfr_Name: Coilcraft; Mfr_Part_Number: MSS1048-152NL
L7 L9-L11 = INDUCTOR-1: Mfr_Name: Wurth; Mfr_Part_Number: 7447789002
R19 R22 R25 R26 R37 R47 R113 R114 R162 = RES: Mfr_Name: Panasonic; Mfr_Part_Number: ERJ-3EKF1002V; Type: Resistor
R20 R23 R31 R39 = RESISTOR: Lead Free Status: No; Mfr_Name: Panasonic; Mfr_Part_Number: ERJ-3EKF1003V; Num Pins: 2; RoHS Compliant: Yes; Type: Resistor
R21 = RES: Mfr_Name: Panasonic; Mfr_Part_Number: ERJ-3EKF2672V; Type: Resistor
R24 = RES: Mfr_Name: Panasonic; Mfr_Part_Number: ERJ-3EKF1241V; Type: Resistor
R27 R34 = RES0603: Mfr_Name: Panasonic; Mfr_Part_Number: ERJ-3EKF2491V
R28 R35 R42 = RES0603: Mfr_Name: Panasonic; Mfr_Part_Number: ERJ-3EKF1002V
R29 R33 = RES0603: Mfr_Name: Panasonic; Mfr_Part_Number: ERJ-3EKF1963V_DNI; Note: DNI
R30 R36 = RES0603: Mfr_Name: Panasonic; Mfr_Part_Number: ERJ-3EKF5622V_DNI; Note: DNI
R32 = RES: Mfr_Name: Panasonic; Mfr_Part_Number: ERJ-3EKF1242V; Type: Resistor
R115 R117-R119 R121-R123 = RES: Mfr_Name: Panasonic; Mfr_Part_Number: ERJ-3GEY0R00V; Type: Resistor
R120 = Res_0603_4.75k: Mfr_Name: Panasonic
TP14 = TESTLOOP_RED: Mfr_Name: Components Corporation; Mfr_Part_Number: TP-105-01-02; TI_SILKTEXT: 1.1V
TP15 = TESTLOOP_WHITE: Mfr_Name: Components Corporation; Mfr_Part_Number: TP-105-01-09; TI_SILKTEXT: PG
TP16 = TESTLOOP_RED: Mfr_Name: Components Corporation; Mfr_Part_Number: TP-105-01-02; TI_SILKTEXT: 0.9V
TP17 = TESTLOOP_RED: Mfr_Name: Components Corporation; Mfr_Part_Number: TP-105-01-02; TI_SILKTEXT: 1.5V
TP18 = TESTLOOP_RED: Mfr_Name: Components Corporation; Mfr_Part_Number: TP-105-01-02; TI_SILKTEXT: 1.8V
U7 = TPS74401RGW
U8 U10 U13 = TPS54620RGY_0
U9 U12 U15 = TPS54325PWP
U11 = TPS51100DGQ
C77 = CAP_SMD_POL_1: CAP, ELECTROLYTIC, 47uF, CaseE, 20%, 35VDC, 0.4 ESR; Altera Part No.: ALTP03-09837-00; DEVICE: CAP_47UF_8MM; Dielectric: Electrolytic; Mfr_Name: Panasonic; Mfr_Part_Number: EEE-HA1V470UP; Working Voltage: 35V
C78 = CAP_SMD_POL_2: CAP, Electrolytic, 680uF, FK, 20%, 35V; Dielectric: Electrolytic; Mfr_Name: Panasonic; Mfr_Part_Number: EEV-FK1V681Q; Tolerance: 20%; Working Voltage: 35V
C80 C81 = CAPACITOR_NP_4: Mfr_Name: Murata; Mfr_Part_Number: GRM32DR71C106KA01L; TOL: 10%
C87 = CAP0603: Mfr_Name: Murata; Mfr_Part_Number: GRM188R71C104KA01D_DNI; Note: DNI; PART_NUMBER: ECJ-1VB1C104K; TOL: 10%; Voltage: 16V
C88 = CAP_1210: Mfr_Name: Murata; Mfr_Part_Number: GRM32ER60J107ME20L
C90 = CAP0603: Mfr_Name: AVX; Mfr_Part_Number: 06035C122KAT2A
C92 = CAP: Mfr_Name: Taiyo Yuden; Mfr_Part_Number: AMK107BJ226MA-T; TOL: 20%; VOLTAGE: 4V
C93 = CAP0603: Mfr_Name: AVX; Mfr_Part_Number: 0603YC223KAT2A
C295 = CAP_0603_10uF: Mfr_Name: Murata
C296 = CAP_0603_.027uF
C355 = CAP_0603_4.7pF
D11 = DIODE_SS3P6L: Mfr_Name: Vishay
D12 = LED_GREEN_1206: Mfr_Name: Liteon; TI_SILKTEXT: 5V IN
D14 = MBRB2515L_5
F1 = FUSE_0: Mfr_Name: TE Connectivity; Mfr_Part_Number: 1206SFF200F/63-2_DNI; Note: DNI
J9 = CON_THRT_BANANA_JACK_RED: TI_Silktext: +5V
J10 = HEADER_1x2_100: TI_SILKTEXT: 3.3V _ GND
J12 = CONN_JACK_PWR: Mfr_Name: SWITCHCRAFT; Mfr_Part_Number: RAPC722
J19 = CON_THRT_BANANA_JACK_BLK: TI_Silktext: GND
L12 = IND_0805_H: Mfr_Name: Coilcraft; Mfr_Part_Number: MSS1038-103NL
Q1 = PWR_MOSFET_CSD17313Q2: Mfr_Name: Texas Instruments
R38 = RES: Mfr_Name: Panasonic; Mfr_Part_Number: ERJ-3EKF3402V; Type: Resistor
R40 = RES: Mfr_Name: Panasonic; Mfr_Part_Number: ERJ-3EKF2152V; Type: Resistor
R41 = RES0603: Mfr_Name: Panasonic; Mfr_Part_Number: ERJ-3EKF1541V
R43 = RES0603: Mfr_Name: Panasonic; Mfr_Part_Number: ERJ-3EKF2003V_DNI; Note: DNI
R44 = RES0603: Mfr_Name: Panasonic; Mfr_Part_Number: ERJ-3EKF5762V_DNI; Note: DNI
R48 = RES: Mfr_Name: Panasonic; Mfr_Part_Number: ERJ-3EKF3012V; Type: Resistor
R145 = Res_0603_38.3K: Mfr_Name: Panasonic
R146 R147 = Res_0603_10k: Mfr_Name: Panasonic
R148 = Res_0603_80.6K: Mfr_Name: Panasonic
R157 = RES: Mfr_Name: Panasonic; Mfr_Part_Number: ERJ-3GEY0R00V_DNI; Note: DNI; Type: Resistor
R158 = RES: Mfr_Name: Panasonic; Mfr_Part_Number: ERJ-2RKF1001X
TP19 = TESTLOOP_RED: Mfr_Name: Components Corporation; Mfr_Part_Number: TP-105-01-02; TI_SILKTEXT: 3.0V
TP20 = TESTLOOP_RED: Mfr_Name: Components Corporation; Mfr_Part_Number: TP-105-01-02; TI_SILKTEXT: 2.5V
TP21 = TESTLOOP_RED: Mfr_Name: Components Corporation; Mfr_Part_Number: TP-105-01-02; TI_SILKTEXT: 3.3V
U19 = TPS2400: Mfr_Name: Texas Instruments; Mfr_Part_Number: TPS2400DBVT
U20 = TPS61175: Mfr_Name: Texas Instruments

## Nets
0.9V: C53.2 C54.1 L6.2 R24.2 TP16.1(TP) ; also on sheet 7 18 20
0.9V_DDR: C71.1 U11.3(VTT) U11.5(VTTSNS) ; also on sheet 6
0.9V_VREF: C75.2 U11.6(VTTREF) ; also on sheet 6
1.1V: C47.2 R19.2 TP14.1(TP) U7.1(OUT) U7.18(OUT3) U7.19(OUT2) U7.20(OUT1) ; also on sheet 18 20
1.5V: C62.1 L7.2 R26.2 TP17.1(TP) U9.1(VO) ; also on sheet 18 20
1.8V: C65.2 C66.1 C72.1 J8.1 JP1.1(Pin1) JP4.1(Pin1) L8.2 R32.2 TP18.1(TP) U11.1(VDDQSNS) U11.2(VLDOIN) ; also on sheet 6 9 18 20
2.5V: C48.2 C87.2 C88.1 L10.2 R22.1 R40.2 TP20.1(TP) U7.5(IN1) U7.6(IN2) U7.7(IN3) U7.8(IN4) ; also on sheet 18 20
3.0V: C42.1 C43.1 C44.1 C100.1 C142.1 C414.2 C417.2 C419.2 C422.2 JP1.3(Pin3) JP4.3(Pin3) L11.2 R48.2 R78.1 TP19.1(TP) U15.1(VO) U16.23(VCCB) U16.24(VCCB) U17.23(VCCB) U17.24(VCCB) U21.5(VCC) U22.5(VCC) U23.6(VCCB) U24.6(VCCB) U25.5(VCC) U26.5(VCC) ; also on sheet 18 20 21
3.3V: C85.1 J10.1 L9.2 R38.2 TP21.1(TP) U12.1(VO) ; also on sheet 2 7 18
5V_IN: C50.2 C52.1 C55.1 C56.1 C67.1 C68.1 C73.1 C79.1 C92.1 C96.1 C294.2 C355.1 J9.1(CENTER) J9.2(GND) L12.1 R29.1 R33.1 R43.1 R113.2 R114.2 R120.1 U7.10(BIAS) U8.4(PVIN) U8.5(PVIN) U8.6(VIN) U9.13(VIN) U9.14(VCC) U10.4(PVIN) U10.5(PVIN) U10.6(VIN) U11.10(VIN) U12.13(VIN) U12.14(VCC) U13.4(PVIN) U13.5(PVIN) U13.6(VIN) U15.13(VIN) U15.14(VCC) U20.3(VIN) ; also on sheet 2 18
5VIN: D14.4 F1.1 J12.1 Q1.1(D1) Q1.2(D2) Q1.5(D5) Q1.6(D6) Q1.8(D8) U19.5(VIN)
6.0V_OUT: C296.1 D11.3 R145.1 ; also on sheet 4
GND: C42.2 C43.2 C44.2 C47.1 C48.1 C49.1 C50.1 C52.2 C53.1 C54.2 C55.2 C56.2 C57.2 C58.2 C60.1 C61.1 C62.2 C63.2 C65.1 C66.2 C67.2 C68.2 C69.2 C70.2 C71.2 C72.2 C73.2 C74.2 C75.1 C76.1 C77.2 C78.2 C79.2 C80.2 C81.2 C83.1 C84.1 C85.2 C87.1 C88.2 C90.2 C91.2 C92.2 C93.2 C96.2 C98.1 C99.1 C100.2 C142.2 C294.1 C295.2 C296.2 C355.2 C414.1 C415.1 C416.1 C417.1 C419.1 C420.1 C421.1 C422.1 D12.2(CATHODE) D14.1 D14.3 J8.2 J10.2 J11.2(GND) J11.3(GND) J11.4(GND) J11.5(GND) J12.2 J12.3 J14.2(GND) J14.3(GND) J14.4(GND) J14.5(GND) J15.2(GND) J15.3(GND) J15.4(GND) J15.5(GND) J16.2(GND) J16.3(GND) J16.4(GND) J16.5(GND) J17.2(GND) J17.3(GND) J17.4(GND) J17.5(GND) J19.1(CENTER) J19.2(GND) JP2.3(Pin3) JP3.3(Pin3) R21.2 R23.1 R25.1 R28.2 R30.2 R31.1 R35.2 R36.2 R37.1 R39.1 R42.2 R44.2 R47.1 R106.2 R146.2 R147.2 R148.2 R158.2 SJP1.3(Pin3) SJP4.3(Pin3) SJP5.3(Pin3) SJP6.3(Pin3) U5.A5(RDN7A/DIFFIO_RX_T1N/DIFFOUT_T2N/DQSN1T) U5.B5(RUP7A/DIFFIO_RX_T1P/DIFFOUT_T2P/DQS1T) U7.2(NC1) U7.3(NC2) U7.4(NC3) U7.12(GND) U7.13(NC4) U7.14(NC5) U7.17(NC6) U7.21(PWRPAD) U8.2(GND) U8.3(GND) U8.15(PWRPAD) U9.5(GND) U9.8(PGND1) U9.9(PGND2) U9.15(PWRPAD) U10.2(GND) U10.3(GND) U10.15(PWRPAD) U11.4(PGND) U11.8(GND) U11.11(PWRPAD) U12.5(GND) U12.8(PGND1) U12.9(PGND2) U12.15(PWRPAD) U13.2(GND) U13.3(GND) U13.15(PWRPAD) U15.5(GND) U15.8(PGND1) U15.9(PGND2) U15.15(PWRPAD) U16.11(GND) U16.12(GND) U16.13(GND) U17.11(GND) U17.12(GND) U17.13(GND) U19.2(GND) U20.6(SYNC) U20.7(AGND) U20.11(GND) U20.12(PGND) U20.13(PGND) U20.14(PGND) U20.15(PWRPAD) U21.2(GND) U22.2(GND) U23.2(GND) U24.2(GND) U25.2(GND) U26.2(GND) ; also on sheet 2 3 4 5 6 7 9 18 19 20 21
ADBUS0: U5.D22(IO_8A_D22/DQ13T/DIFFOUT_T52N) ; also on sheet 5
ADBUS1: U5.J20(IO_8A_J20/DIFFOUT_T46P) ; also on sheet 5
ADBUS2: U5.D25(IO_8A_D25/DQS15T/DIFFIO_RX_T29P/DIFFOUT_T57P) ; also on sheet 5
ADBUS3: U5.F21(IO_8A_F21/DQ13T/DIFFOUT_T52P) ; also on sheet 5
ADBUS4: U5.D8(IO_7A_D8/DQ3T/DIFFOUT_T7P) ; also on sheet 5
ADBUS5: U5.D9(IO_7A_D9/DQ3T/DIFFOUT_T9P) ; also on sheet 5
ADBUS6: U5.E11(IO_7A_E11/DQS5T/DIFFIO_RX_T7P/DIFFOUT_T14P) ; also on sheet 5
ADBUS7: U5.E12(IO_7A_E12/DQ5T/DIFFOUT_T15P) ; also on sheet 5
ADC_0: U5.C10(IO_7A_C10/DQSN3T/DIFFIO_RX_T4N/DIFFOUT_T8N) U16.21(B1)
ADC_1: U5.C12(IO_7A_C12/DQ5T/DIFFOUT_T13N) U16.20(B2)
ADC_2: U5.C13(IO_7A_C13/DQ6T/DIFFOUT_T17P) U16.19(B3)
ADC_3: U5.C9(IO_7A_C9/DQ2T/DIFFOUT_T5P) U16.18(B4)
ADC_4: U5.D10(IO_7A_D10/DQS3T/DIFFIO_RX_T4P/DIFFOUT_T8P) U16.17(B5)
ADC_5: U5.D11(IO_7A_D11/DQSN5T/DIFFIO_RX_T7N/DIFFOUT_T14N) U16.16(B6)
ADC_6: U5.D12(IO_7A_D12/DQ5T/DIFFOUT_T13P) U16.15(B7)
ADC_7: U5.D13(IO_7A_D13/DQ5T/DIFFOUT_T15N) U24.3(A)
ADC_BUF_PWR: C420.2 C421.2 JP3.1(Pin1) JP4.2(Pin2) SJP4.1(Pin1) SJP6.1(Pin1) U16.1(VCCA) U24.1(VCCA)
ADC_GPIO_0: U16.3(A1) ; also on sheet 3
ADC_GPIO_1: U16.4(A2) ; also on sheet 3
ADC_GPIO_2: U16.5(A3) ; also on sheet 3
ADC_GPIO_3: U16.6(A4) ; also on sheet 3
ADC_GPIO_4: U16.7(A5) ; also on sheet 3
ADC_GPIO_5: U16.8(A6) ; also on sheet 3
ADC_GPIO_6: U16.9(A7) ; also on sheet 3
ADC_GPIO_7: U24.4(B) ; also on sheet 3
ADC_TRIG: U26.3(2A) ; also on sheet 3
BDBUS0: U5.D23(IO_8A_D23/DQS13T/DIFFIO_RX_T26P/DIFFOUT_T51P) ; also on sheet 5
BDBUS1: U5.J21(IO_8A_J21/DIFFIO_RX_T23P/DIFFOUT_T45P) ; also on sheet 5
BDBUS2: U5.D26(IO_8A_D26/DQ15T/DIFFOUT_T58N) ; also on sheet 5
BDBUS3: U5.F22(IO_8A_F22/DQ13T/DIFFOUT_T50P) ; also on sheet 5
BDBUS4: U5.B11(IO_7A_B11/DQS6T/DIFFIO_RX_T8P/DIFFOUT_T16P) ; also on sheet 5
BDBUS5: U5.B12(IO_7A_B12/DQ6T/DIFFIO_RX_T9P/DIFFOUT_T18P) ; also on sheet 5
BDBUS6: U5.B9(IO_7A_B9/DQ2T/DIFFIO_RX_T3P/DIFFOUT_T6P) ; also on sheet 5
BDBUS7: U5.L17(IO_7C_L17/DQ9T/DIFFOUT_T27P) ; also on sheet 5
CDBUS0: U5.D24(IO_8A_D24/DQ14T/DIFFIO_RX_T27N/DIFFOUT_T53N) ; also on sheet 5
CDBUS1: U5.H21(IO_8A_H21/DIFFIO_RX_T23N/DIFFOUT_T45N) ; also on sheet 5
CDBUS2: U5.D27(IO_8A_D27/DQ15T/DIFFOUT_T58P) ; also on sheet 5
CDBUS3: U5.F23(IO_8A_F23/DQS14T/DIFFIO_RX_T28P/DIFFOUT_T55P) ; also on sheet 5
CDBUS4: U5.E8(IO_7A_E8/DQ3T/DIFFOUT_T7N) ; also on sheet 5
CDBUS5: U5.F10(IO_7A_F10/DQ3T/DIFFOUT_T9N) ; also on sheet 5
CDBUS6: U5.F11(IO_7A_F11/DQ4T/DIFFIO_RX_T6N/DIFFOUT_T12N) ; also on sheet 5
CDBUS7: U5.F13(IO_7A_F13/DQ4T/DIFFOUT_T11N) ; also on sheet 5
CMOS_PORT0_1: U5.L18(IO_8C_L18/PLL_T1_CLKOUT3/DIFFOUT_T38P) ; also on sheet 3
CMOS_PORT0_2: U5.K18(IO_8C_K18/PLL_T1_CLKOUT0P/DIFFOUT_T36P) ; also on sheet 3
CMOS_PORT0_3: U5.K19(IO_8C_K19/DIFFIO_RX_T19P/DIFFOUT_T37P) ; also on sheet 3
CMOS_PORT0_4: U5.J18(IO_8C_J18/PLL_T1_CLKOUT0N/DIFFOUT_T36N) ; also on sheet 3
CMOS_PORT0_5: U5.J19(IO_8C_J19/DIFFIO_RX_T19N/DIFFOUT_T37N) ; also on sheet 3
CMOS_PORT0_6: U5.F19(IO_8C_F19/DQ10T/DIFFOUT_T40P) ; also on sheet 3
CMOS_PORT0_7: U5.F20(IO_8C_F20/DQ10T/DIFFOUT_T40N) ; also on sheet 3
CMOS_PORT0_8: U5.E20(IO_8C_E20/DQS10T/DIFFIO_RX_T21P/DIFFOUT_T41P) ; also on sheet 3
CMOS_PORT0_9: U5.E21(IO_8C_E21/DQS11T/DIFFIO_RX_T22P/DIFFOUT_T43P) ; also on sheet 3
CMOS_PORT0_10: U5.D18(IO_8C_D18/PLL_T1_FBP/CLKOUT1/DIFFIO_RX_T18P/DIFFOUT_T35P) ; also on sheet 3
CMOS_PORT0_11: U5.D19(IO_8C_D19/DQ10T/DIFFIO_RX_T20P/DIFFOUT_T39P) ; also on sheet 3
CMOS_PORT0_12: U5.D20(IO_8C_D20/DQSN10T/DIFFIO_RX_T21N/DIFFOUT_T41N) ; also on sheet 3
CMOS_PORT0_13: U5.D21(IO_8C_D21/DQSN11T/DIFFIO_RX_T22N/DIFFOUT_T43N) ; also on sheet 3
CMOS_PORT0_14: U5.C18(IO_8C_C18/PLL_T1_FBN/CLKOUT2/DIFFIO_RX_T18N/DIFFOUT_T35N) ; also on sheet 3
CMOS_PORT0_15: U5.C19(IO_8C_C19/DQ10T/DIFFIO_RX_T20N/DIFFOUT_T39N) ; also on sheet 3
CMOS_PORT0_16: U5.C20(IO_8C_C20/DQ11T/DIFFOUT_T42P) ; also on sheet 3
CMOS_PORT0_17: U5.C21(IO_8C_C21/DQ11T/DIFFOUT_T42N) ; also on sheet 3
CMOS_PORT0_18: U5.B21(IO_8C_B21/DQ11T/DIFFOUT_T44N) ; also on sheet 3
CMOS_PORT0_19: U5.A21(IO_8C_A21/DQ11T/DIFFOUT_T44P) ; also on sheet 3
CMOS_PORT0_20: U5.A30(RDN8A/DIFFIO_RX_T32N/DIFFOUT_T63N/DQSN17T) ; also on sheet 3
CMOS_PORT0_21: U5.B29(IO_8A_B29/DQ17T/DIFFOUT_T62N) ; also on sheet 3
CMOS_PORT1_1: U5.K17(IO_7C_K17/DIFFIO_RX_T15P/DIFFOUT_T30P) ; also on sheet 3
CMOS_PORT1_2: U5.K16(IO_7C_K16/DQS9T/DIFFIO_RX_T14P/DIFFOUT_T28P) ; also on sheet 3
CMOS_PORT1_3: U5.J17(IO_7C_J17/DIFFIO_RX_T15N/DIFFOUT_T30N) ; also on sheet 3
CMOS_PORT1_4: U5.J16(IO_7C_J16/DQSN9T/DIFFIO_RX_T14N/DIFFOUT_T28N) ; also on sheet 3
CMOS_PORT1_5: U5.B14(IO_7C_B14/DQ7T/DIFFOUT_T21P) ; also on sheet 3
CMOS_PORT1_6: U5.G16(IO_7C_G16/DQ9T/DIFFOUT_T29P) ; also on sheet 3
CMOS_PORT1_7: U5.F15(IO_7C_F15/DQ9T/DIFFOUT_T29N) ; also on sheet 3
CMOS_PORT1_8: U5.E14(IO_7C_E14/DQS7T/DIFFIO_RX_T11P/DIFFOUT_T22P) ; also on sheet 3
CMOS_PORT1_9: U5.E15(IO_7C_E15/DQS8T/DIFFIO_RX_T12P/DIFFOUT_T24P) ; also on sheet 3
CMOS_PORT1_10: U5.E17(IO_7C_E17/DQ9T/DIFFOUT_T27N) ; also on sheet 3
CMOS_PORT1_11: U5.D14(IO_7C_D14/DQSN7T/DIFFIO_RX_T11N/DIFFOUT_T22N) ; also on sheet 3
CMOS_PORT1_12: U5.D15(IO_7C_D15/DQSN8T/DIFFIO_RX_T12N/DIFFOUT_T24N) ; also on sheet 3
CMOS_PORT1_13: U5.D16(IO_7C_D16/DQ8T/DIFFIO_RX_T13P/DIFFOUT_T26P) ; also on sheet 3
CMOS_PORT1_14: U5.D17(IO_7C_D17/DQ8T/DIFFOUT_T25N) ; also on sheet 3
CMOS_PORT1_15: U5.C14(IO_7C_C14/DQ7T/DIFFOUT_T23P) ; also on sheet 3
CMOS_PORT1_16: U5.C15(IO_7C_C15/DQ7T/DIFFOUT_T23N) ; also on sheet 3
CMOS_PORT1_17: U5.C16(IO_7C_C16/DQ8T/DIFFIO_RX_T13N/DIFFOUT_T26N) ; also on sheet 3
CMOS_PORT1_18: U5.C17(IO_7C_C17/DQ8T/DIFFOUT_T25P) ; also on sheet 3
CMOS_PORT1_19: U5.A14(IO_7C_A14/DQ7T/DIFFOUT_T21N) ; also on sheet 3
CMOS_PORT1_20: U5.A31(IO_8A_A31/DQ17T/DIFFOUT_T64N) ; also on sheet 3
CMOS_PORT1_21: U5.B30(RUP8A/DIFFIO_RX_T32P/DIFFOUT_T63P/DQS17T) ; also on sheet 3
CMOS_SP1: U5.A10(IO_7A_A10/DQ2T/DIFFOUT_T5N) ; also on sheet 4
CMOS_SP2: U5.A11(IO_7A_A11/DQSN6T/DIFFIO_RX_T8N/DIFFOUT_T16N) ; also on sheet 4
CMOS_SP3: U5.A12(IO_7A_A12/DQ6T/DIFFIO_RX_T9N/DIFFOUT_T18N) ; also on sheet 4
CMOS_SP4: U5.A13(IO_7A_A13/DQ6T/DIFFOUT_T17N) ; also on sheet 4
CMOS_SP5: U5.A4(IO_7A_A4/DQ1T/DIFFOUT_T1P) ; also on sheet 4
CMOS_SP6: U5.A6(IO_7A_A6/DQ1T/DIFFOUT_T1N) ; also on sheet 4
CMOS_SP7: U5.A7(IO_7A_A7/DQ1T/DIFFOUT_T3N) ; also on sheet 4
DAC_0: U5.F14(IO_7A_F14/DIFFOUT_T19N) U17.21(B1)
DAC_1: U5.G11(IO_7A_G11/DQ4T/DIFFIO_RX_T6P/DIFFOUT_T12P) U17.20(B2)
DAC_2: U5.G12(IO_7A_G12/DQSN4T/DIFFIO_RX_T5N/DIFFOUT_T10N) U17.19(B3)
DAC_3: U5.G13(IO_7A_G13/DQ4T/DIFFOUT_T11P) U17.18(B4)
DAC_4: U5.H12(IO_7A_H12/DQS4T/DIFFIO_RX_T5P/DIFFOUT_T10P) U17.17(B5)
DAC_5: U5.H14(IO_7A_H14/DIFFOUT_T19P) U17.16(B6)
DAC_6: U5.H15(IO_7A_H15/DIFFIO_RX_T10N/DIFFOUT_T20N) U17.15(B7)
DAC_7: U5.J15(IO_7A_J15/DIFFIO_RX_T10P/DIFFOUT_T20P) U23.3(A)
DAC_BUF_PWR: C415.2 C416.2 JP1.2(Pin2) JP2.1(Pin1) SJP1.1(Pin1) SJP5.1(Pin1) U17.1(VCCA) U23.1(VCCA)
DAC_GPIO_0: U17.3(A1) ; also on sheet 4
DAC_GPIO_1: U17.4(A2) ; also on sheet 4
DAC_GPIO_2: U17.5(A3) ; also on sheet 4
DAC_GPIO_3: U17.6(A4) ; also on sheet 4
DAC_GPIO_4: U17.7(A5) ; also on sheet 4
DAC_GPIO_5: U17.8(A6) ; also on sheet 4
DAC_GPIO_6: U17.9(A7) ; also on sheet 4
DAC_GPIO_7: U23.4(B) ; also on sheet 4
DB0N: U5.AG12(IO_5A_AG12/DQ3R/DIFFIO_TX_R6N/DIFFOUT_R11N) ; also on sheet 4
DB0P: U5.AF12(IO_5A_AF12/DQ3R/DIFFIO_TX_R6P/DIFFOUT_R11P) ; also on sheet 4
DB1N: U5.AF11(IO_5A_AF11/DQ1R/DIFFIO_TX_R3N/DIFFOUT_R5N) ; also on sheet 4
DB1P: U5.AE12(IO_5A_AE12/DQ1R/DIFFIO_TX_R3P/DIFFOUT_R5P) ; also on sheet 4
DB2N: U5.AD11(IO_5A_AD11/DIFFIO_TX_R8N/DIFFOUT_R15N) ; also on sheet 4
DB2P: U5.AD12(IO_5A_AD12/DIFFIO_TX_R8P/DIFFOUT_R15P) ; also on sheet 4
DB3N: U5.AE9(IO_5A_AE9/DQ3R/DIFFIO_TX_R5N/DIFFOUT_R9N) ; also on sheet 4
DB3P: U5.AE10(IO_5A_AE10/DQ3R/DIFFIO_TX_R5P/DIFFOUT_R9P) ; also on sheet 4
DB4N: U5.AE8(IO_5A_AE8/DQ2R/DIFFIO_TX_R4N/DIFFOUT_R7N) ; also on sheet 4
DB4P: U5.AF9(IO_5A_AF9/DQ2R/DIFFIO_TX_R4P/DIFFOUT_R7P) ; also on sheet 4
DB5N: U5.AF10(IO_5A_AF10/DQ4R/DIFFIO_TX_R7N/DIFFOUT_R13N) ; also on sheet 4
DB5P: U5.AG11(IO_5A_AG11/DQ4R/DIFFIO_TX_R7P/DIFFOUT_R13P) ; also on sheet 4
DB6N: U5.AC11(IO_5A_AC11/DIFFIO_TX_R1N/DIFFOUT_R1N) ; also on sheet 4
DB6P: U5.AC12(IO_5A_AC12/DIFFIO_TX_R1P/DIFFOUT_R1P) ; also on sheet 4
DB7N: U5.AB9(IO_5C_AB9/DQ5R/DIFFIO_TX_R10N/DIFFOUT_R19N) ; also on sheet 4
DB7P: U5.AC10(IO_5C_AC10/DQ5R/DIFFIO_TX_R10P/DIFFOUT_R19P) ; also on sheet 4
DB8N: U5.AB10(IO_5C_AB10/DIFFIO_TX_R9N/DIFFOUT_R17N) ; also on sheet 4
DB8P: U5.AB11(IO_5C_AB11/DIFFIO_TX_R9P/DIFFOUT_R17P) ; also on sheet 4
DB9N: U5.AB12(IO_5A_AB12/DQ1R/DIFFIO_TX_R2N/DIFFOUT_R3N) ; also on sheet 4
DB9P: U5.AA12(IO_5A_AA12/DQ1R/DIFFIO_TX_R2P/DIFFOUT_R3P) ; also on sheet 4
DB10N: U5.Y12(IO_5C_Y12/DQ6R/DIFFIO_TX_R12N/DIFFOUT_R23N) ; also on sheet 4
DB10P: U5.W12(IO_5C_W12/DQ6R/DIFFIO_TX_R12P/DIFFOUT_R23P) ; also on sheet 4
DB11N: U5.AA8(IO_5C_AA8/DQ7R/DIFFIO_TX_R13N/DIFFOUT_R25N) ; also on sheet 4
DB11P: U5.AA9(IO_5C_AA9/DQ7R/DIFFIO_TX_R13P/DIFFOUT_R25P) ; also on sheet 4
DB12N: U5.Y10(IO_5C_Y10/DQ6R/DIFFIO_TX_R11N/DIFFOUT_R21N) ; also on sheet 4
DB12P: U5.AA11(IO_5C_AA11/DQ6R/DIFFIO_TX_R11P/DIFFOUT_R21P) ; also on sheet 4
DB13N: U5.V10(IO_5C_V10/DIFFIO_TX_R14N/DIFFOUT_R27N) ; also on sheet 4
DB13P: U5.W11(IO_5C_W11/DIFFIO_TX_R14P/DIFFOUT_R27P) ; also on sheet 4
DB14N: U5.R10(IO_6C_R10/DQ8R/DIFFIO_TX_R16N/DIFFOUT_R32N) ; also on sheet 4
DB14P: U5.R11(IO_6C_R11/DQ8R/DIFFIO_TX_R16P/DIFFOUT_R32P) ; also on sheet 4
DB15N: U5.U10(IO_6C_U10/DQ9R/DIFFIO_TX_R17N/DIFFOUT_R34N) ; also on sheet 4
DB15P: U5.T11(IO_6C_T11/DQ9R/DIFFIO_TX_R17P/DIFFOUT_R34P) ; also on sheet 4
DBCLKN: U5.U9(IO_6C_U9/PLL_R2_CLKOUT0N/DIFFIO_TX_R15N/DIFFOUT_R30N) ; also on sheet 4
DBCLKP: U5.T9(IO_6C_T9/PLL_R2_FB_CLKOUT0P/DIFFIO_TX_R15P/DIFFOUT_R30P) ; also on sheet 4
DDBUS4: U5.M18(IO_8C_M18/PLL_T1_CLKOUT4/DIFFOUT_T38N) ; also on sheet 5
DDBUS5: U5.C22(IO_8A_C22/DQ12T/DIFFOUT_T48N) ; also on sheet 5
DDR2_BA0: U5.AE15(IO_4A_AE15/DIFFIO_RX_B23P/DIFFOUT_B45P) ; also on sheet 6
DDR2_BA1: U5.AF15(IO_4A_AF15/DIFFIO_RX_B23N/DIFFOUT_B45N) ; also on sheet 6
DDR2_BA2: U5.AF14(IO_4A_AF14/DIFFOUT_B46P) ; also on sheet 6
DDR2_CAS_n: U5.AD17(IO_4C_AD17/DQ9B/DIFFOUT_B38P) ; also on sheet 6
DDR2_CKE0: U5.AJ12(IO_4A_AJ12/DQ13B/DIFFOUT_B50P) ; also on sheet 6
DDR2_CKE1: U5.AJ20(IO_3C_AJ20/DQ8B/DIFFOUT_B25N) ; also on sheet 6
DDR2_CLK_n0: U5.AF16(IO_4C_AF16/DQSN9B/DIFFIO_RX_B19N/DIFFOUT_B37N) ; also on sheet 6
DDR2_CLK_n1: U5.AJ15(IO_4C_AJ15/DQ9B/DIFFOUT_B36N) ; also on sheet 6
DDR2_CLK_p0: U5.AE16(IO_4C_AE16/DQS9B/DIFFIO_RX_B19P/DIFFOUT_B37P) ; also on sheet 6
DDR2_CLK_p1: U5.AH16(IO_4C_AH16/DQ9B/DIFFOUT_B36P) ; also on sheet 6
DDR2_CS_n0: U5.AK17(IO_4C_AK17/DQ9B/DIFFOUT_B38N) ; also on sheet 6
DDR2_CS_n1: U5.AL18(IO_3C_AL18/PLL_B1_FBP/CLKOUT1/DIFFIO_RX_B15P/DIFFOUT_B30P) ; also on sheet 6
DDR2_DM0: U5.AP10(IO_4A_AP10/DQ16B/DIFFOUT_B60N) ; also on sheet 6
DDR2_DM1: U5.AK12(IO_4A_AK12/DQ13B/DIFFOUT_B52P) ; also on sheet 6
DDR2_DM2: U5.AJ19(IO_3C_AJ19/DQ8B/DIFFOUT_B25P) ; also on sheet 6
DDR2_DM3: U5.AH13(IO_4A_AH13/DQ14B/DIFFIO_RX_B27P/DIFFOUT_B53P) ; also on sheet 6
DDR2_DM4: U5.AM26(IO_3A_AM26/DQ2B/DIFFOUT_B5N) ; also on sheet 6
DDR2_DM5: U5.AH22(IO_3A_AH22/DQ5B/DIFFOUT_B15N) ; also on sheet 6
DDR2_DM6: U5.AM17(IO_4C_AM17/DQ10B/DIFFOUT_B40P) ; also on sheet 6
DDR2_DM7: U5.AM25(IO_3A_AM25/DQSN3B/DIFFIO_RX_B4N/DIFFOUT_B8N) ; also on sheet 6
DDR2_DQ0: U5.AP4(IO_4A_AP4/DQ17B/DIFFOUT_B64P) ; also on sheet 6
DDR2_DQ1: U5.AP5(RDN4A/DIFFIO_RX_B32N/DIFFOUT_B63N/DQSN17B) ; also on sheet 6
DDR2_DQ2: U5.AP6(IO_4A_AP6/DQ17B/DIFFOUT_B64N) ; also on sheet 6
DDR2_DQ3: U5.AP7(IO_4A_AP7/DQ17B/DIFFOUT_B62N) ; also on sheet 6
DDR2_DQ4: U5.AN6(IO_4A_AN6/DQ17B/DIFFOUT_B62P) ; also on sheet 6
DDR2_DQ5: U5.AN5(RUP4A/DIFFIO_RX_B32P/DIFFOUT_B63P/DQS17B) ; also on sheet 6
DDR2_DQ6: U5.AN9(IO_4A_AN9/DQ16B/DIFFIO_RX_B30P/DIFFOUT_B59P) ; also on sheet 6
DDR2_DQ7: U5.AP9(IO_4A_AP9/DQ16B/DIFFIO_RX_B30N/DIFFOUT_B59N) ; also on sheet 6
DDR2_DQ8: U5.AM13(IO_4A_AM13/DQ12B/DIFFOUT_B48P) ; also on sheet 6
DDR2_DQ9: U5.AL12(IO_4A_AL12/DQ13B/DIFFOUT_B52N) ; also on sheet 6
DDR2_DQ10: U5.AL13(IO_4A_AL13/DQ13B/DIFFOUT_B50N) ; also on sheet 6
DDR2_DQ11: U5.AP13(IO_4A_AP13/DQ12B/DIFFOUT_B48N) ; also on sheet 6
DDR2_DQ12: U5.AM11(IO_4A_AM11/DQSN13B/DIFFIO_RX_B26N/DIFFOUT_B51N) ; also on sheet 6
DDR2_DQ13: U5.AN12(IO_4A_AN12/DQ12B/DIFFIO_RX_B24P/DIFFOUT_B47P) ; also on sheet 6
DDR2_DQ14: U5.AL11(IO_4A_AL11/DQS13B/DIFFIO_RX_B26P/DIFFOUT_B51P) ; also on sheet 6
DDR2_DQ15: U5.AP12(IO_4A_AP12/DQ12B/DIFFIO_RX_B24N/DIFFOUT_B47N) ; also on sheet 6
DDR2_DQ16: U5.AL21(IO_3C_AL21/DQSN7B/DIFFIO_RX_B11N/DIFFOUT_B22N) ; also on sheet 6
DDR2_DQ17: U5.AM21(IO_3C_AM21/DQ7B/DIFFOUT_B23N) ; also on sheet 6
DDR2_DQ18: U5.AL19(IO_3C_AL19/DQ8B/DIFFIO_RX_B13P/DIFFOUT_B26P) ; also on sheet 6
DDR2_DQ19: U5.AM19(IO_3C_AM19/DQ8B/DIFFIO_RX_B13N/DIFFOUT_B26N) ; also on sheet 6
DDR2_DQ20: U5.AN21(IO_3C_AN21/DQ7B/DIFFOUT_B21N) ; also on sheet 6
DDR2_DQ21: U5.AK21(IO_3C_AK21/DQS7B/DIFFIO_RX_B11P/DIFFOUT_B22P) ; also on sheet 6
DDR2_DQ22: U5.AM20(IO_3C_AM20/DQ7B/DIFFOUT_B23P) ; also on sheet 6
DDR2_DQ23: U5.AP21(IO_3C_AP21/DQ7B/DIFFOUT_B21P) ; also on sheet 6
DDR2_DQ24: U5.AM10(IO_4A_AM10/DQSN15B/DIFFIO_RX_B29N/DIFFOUT_B57N) ; also on sheet 6
DDR2_DQ25: U5.AL10(IO_4A_AL10/DQS15B/DIFFIO_RX_B29P/DIFFOUT_B57P) ; also on sheet 6
DDR2_DQ26: U5.AL9(IO_4A_AL9/DQ15B/DIFFOUT_B58P) ; also on sheet 6
DDR2_DQ27: U5.AL8(IO_4A_AL8/DQ15B/DIFFOUT_B58N) ; also on sheet 6
DDR2_DQ28: U5.AK11(IO_4A_AK11/DQ15B/DIFFOUT_B56N) ; also on sheet 6
DDR2_DQ29: U5.AJ10(IO_4A_AJ10/DQ15B/DIFFOUT_B56P) ; also on sheet 6
DDR2_DQ30: U5.AH11(IO_4A_AH11/DQ14B/DIFFOUT_B54P) ; also on sheet 6
DDR2_DQ31: U5.AH12(IO_4A_AH12/DQ14B/DIFFOUT_B54N) ; also on sheet 6
DDR2_DQ32: U5.AP31(IO_3A_AP31/DQ1B/DIFFOUT_B1N) ; also on sheet 6
DDR2_DQ33: U5.AN30(RUP3A/DIFFIO_RX_B1P/DIFFOUT_B2P/DQS1B) ; also on sheet 6
DDR2_DQ34: U5.AP30(RDN3A/DIFFIO_RX_B1N/DIFFOUT_B2N/DQSN1B) ; also on sheet 6
DDR2_DQ35: U5.AP29(IO_3A_AP29/DQ1B/DIFFOUT_B1P) ; also on sheet 6
DDR2_DQ36: U5.AN29(IO_3A_AN29/DQ1B/DIFFOUT_B3N) ; also on sheet 6
DDR2_DQ37: U5.AP28(IO_3A_AP28/DQ1B/DIFFOUT_B3P) ; also on sheet 6
DDR2_DQ38: U5.AP26(IO_3A_AP26/DQ2B/DIFFIO_RX_B3N/DIFFOUT_B6N) ; also on sheet 6
DDR2_DQ39: U5.AP25(IO_3A_AP25/DQ2B/DIFFOUT_B5P) ; also on sheet 6
DDR2_DQ40: U5.AP22(IO_3A_AP22/DQ6B/DIFFOUT_B17P) ; also on sheet 6
DDR2_DQ41: U5.AP23(IO_3A_AP23/DQ6B/DIFFIO_RX_B9N/DIFFOUT_B18N) ; also on sheet 6
DDR2_DQ42: U5.AN23(IO_3A_AN23/DQ6B/DIFFIO_RX_B9P/DIFFOUT_B18P) ; also on sheet 6
DDR2_DQ43: U5.AM23(IO_3A_AM23/DQSN5B/DIFFIO_RX_B7N/DIFFOUT_B14N) ; also on sheet 6
DDR2_DQ44: U5.AM22(IO_3A_AM22/DQ6B/DIFFOUT_B17N) ; also on sheet 6
DDR2_DQ45: U5.AL23(IO_3A_AL23/DQS5B/DIFFIO_RX_B7P/DIFFOUT_B14P) ; also on sheet 6
DDR2_DQ46: U5.AL22(IO_3A_AL22/DQ5B/DIFFOUT_B13N) ; also on sheet 6
DDR2_DQ47: U5.AJ22(IO_3A_AJ22/DQ5B/DIFFOUT_B15P) ; also on sheet 6
DDR2_DQ48: U5.AL16(IO_4C_AL16/DQ10B/DIFFIO_RX_B20P/DIFFOUT_B39P) ; also on sheet 6
DDR2_DQ49: U5.AM16(IO_4C_AM16/DQ10B/DIFFIO_RX_B20N/DIFFOUT_B39N) ; also on sheet 6
DDR2_DQ50: U5.AL17(IO_4C_AL17/DQ10B/DIFFOUT_B40N) ; also on sheet 6
DDR2_DQ51: U5.AM15(IO_4C_AM15/DQ11B/DIFFOUT_B42N) ; also on sheet 6
DDR2_DQ52: U5.AM14(IO_4C_AM14/DQ11B/DIFFOUT_B42P) ; also on sheet 6
DDR2_DQ53: U5.AL14(IO_4C_AL14/DQSN11B/DIFFIO_RX_B22N/DIFFOUT_B43N) ; also on sheet 6
DDR2_DQ54: U5.AK14(IO_4C_AK14/DQS11B/DIFFIO_RX_B22P/DIFFOUT_B43P) ; also on sheet 6
DDR2_DQ55: U5.AP14(IO_4C_AP14/DQ11B/DIFFOUT_B44N) ; also on sheet 6
DDR2_DQ56: U5.AL27(IO_3A_AL27/DQ3B/DIFFOUT_B7P) ; also on sheet 6
DDR2_DQ57: U5.AL26(IO_3A_AL26/DQ3B/DIFFOUT_B7N) ; also on sheet 6
DDR2_DQ58: U5.AL25(IO_3A_AL25/DQS3B/DIFFIO_RX_B4P/DIFFOUT_B8P) ; also on sheet 6
DDR2_DQ59: U5.AL24(IO_3A_AL24/DQ4B/DIFFIO_RX_B6N/DIFFOUT_B12N) ; also on sheet 6
DDR2_DQ60: U5.AK24(IO_3A_AK24/DQ4B/DIFFIO_RX_B6P/DIFFOUT_B12P) ; also on sheet 6
DDR2_DQ61: U5.AJ25(IO_3A_AJ25/DQ3B/DIFFOUT_B9N) ; also on sheet 6
DDR2_DQ62: U5.AH24(IO_3A_AH24/DQ4B/DIFFOUT_B11N) ; also on sheet 6
DDR2_DQ63: U5.AH23(IO_3A_AH23/DQ4B/DIFFOUT_B11P) ; also on sheet 6
DDR2_DQS0: U5.AN8(IO_4A_AN8/DQS16B/DIFFIO_RX_B31P/DIFFOUT_B61P) ; also on sheet 6
DDR2_DQS1: U5.AN11(IO_4A_AN11/DQS12B/DIFFIO_RX_B25P/DIFFOUT_B49P) ; also on sheet 6
DDR2_DQS2: U5.AK20(IO_3C_AK20/DQS8B/DIFFIO_RX_B12P/DIFFOUT_B24P) ; also on sheet 6
DDR2_DQS3: U5.AH14(IO_4A_AH14/DQS14B/DIFFIO_RX_B28P/DIFFOUT_B55P) ; also on sheet 6
DDR2_DQS4: U5.AN27(IO_3A_AN27/DQS2B/DIFFIO_RX_B2P/DIFFOUT_B4P) ; also on sheet 6
DDR2_DQS5: U5.AN24(IO_3A_AN24/DQS6B/DIFFIO_RX_B8P/DIFFOUT_B16P) ; also on sheet 6
DDR2_DQS6: U5.AK15(IO_4C_AK15/DQS10B/DIFFIO_RX_B21P/DIFFOUT_B41P) ; also on sheet 6
DDR2_DQS7: U5.AJ23(IO_3A_AJ23/DQS4B/DIFFIO_RX_B5P/DIFFOUT_B10P) ; also on sheet 6
DDR2_DQSn0: U5.AP8(IO_4A_AP8/DQSN16B/DIFFIO_RX_B31N/DIFFOUT_B61N) ; also on sheet 6
DDR2_DQSn1: U5.AP11(IO_4A_AP11/DQSN12B/DIFFIO_RX_B25N/DIFFOUT_B49N) ; also on sheet 6
DDR2_DQSn2: U5.AL20(IO_3C_AL20/DQSN8B/DIFFIO_RX_B12N/DIFFOUT_B24N) ; also on sheet 6
DDR2_DQSn3: U5.AJ14(IO_4A_AJ14/DQSN14B/DIFFIO_RX_B28N/DIFFOUT_B55N) ; also on sheet 6
DDR2_DQSn4: U5.AP27(IO_3A_AP27/DQSN2B/DIFFIO_RX_B2N/DIFFOUT_B4N) ; also on sheet 6
DDR2_DQSn5: U5.AP24(IO_3A_AP24/DQSN6B/DIFFIO_RX_B8N/DIFFOUT_B16N) ; also on sheet 6
DDR2_DQSn6: U5.AL15(IO_4C_AL15/DQSN10B/DIFFIO_RX_B21N/DIFFOUT_B41N) ; also on sheet 6
DDR2_DQSn7: U5.AK23(IO_3A_AK23/DQSN4B/DIFFIO_RX_B5N/DIFFOUT_B10N) ; also on sheet 6
DDR2_ODT0: U5.AG15(IO_4A_AG15/DIFFOUT_B46N) ; also on sheet 6
DDR2_ODT1: U5.AM18(IO_3C_AM18/PLL_B1_FBN/CLKOUT2/DIFFIO_RX_B15N/DIFFOUT_B30N) ; also on sheet 6
DDR2_RAS_n: U5.AE17(IO_4C_AE17/DIFFIO_RX_B18P/DIFFOUT_B35P) ; also on sheet 6
DDR2_WE_n: U5.AF17(IO_4C_AF17/DIFFIO_RX_B18N/DIFFOUT_B35N) ; also on sheet 6
DS3N: U5.N9(IO_6C_N9/DQ10R/DIFFIO_TX_R19P/DIFFOUT_R38P) ; also on sheet 4
DS3P: U5.N8(IO_6C_N8/DQ10R/DIFFIO_TX_R19N/DIFFOUT_R38N) ; also on sheet 4
DS5N: U5.M10(IO_6A_M10/DIFFIO_TX_R21N/DIFFOUT_R42N) ; also on sheet 4
DS5P: U5.L11(IO_6A_L11/DIFFIO_TX_R21P/DIFFOUT_R42P) ; also on sheet 4
EN1: R117.2 R119.2 R123.2 R157.1 ; also on sheet 2
EN2: R122.2 ; also on sheet 2
EN3: R121.2 ; also on sheet 2
EN4: R118.2 ; also on sheet 2
EN5: R115.2 ; also on sheet 2
FTDI_NCE: U5.E23(IO_8A_E23/DQSN14T/DIFFIO_RX_T28N/DIFFOUT_T55N) ; also on sheet 5
FTDI_nCONFIG: U5.E24(IO_8A_E24/DQ14T/DIFFIO_RX_T27P/DIFFOUT_T53P) ; also on sheet 5
Input2_M: U5.AL6(RDN5A/DIFFIO_RX_R1N/DIFFOUT_R2N) ; also on sheet 3
Input2_P: U5.AM7(RUP5A/DIFFIO_RX_R1P/DIFFOUT_R2P) ; also on sheet 3
Input3_M: U5.AM5(IO_5A_AM5/DQSN1R/DIFFIO_RX_R2N/DIFFOUT_R4N) ; also on sheet 3
Input3_P: U5.AM6(IO_5A_AM6/DQS1R/DIFFIO_RX_R2P/DIFFOUT_R4P) ; also on sheet 3
Input4_M: U5.AL5(IO_5A_AL5/DQSN2R/DIFFIO_RX_R3N/DIFFOUT_R6N) ; also on sheet 3
Input4_P: U5.AK6(IO_5A_AK6/DQS2R/DIFFIO_RX_R3P/DIFFOUT_R6P) ; also on sheet 3
Input5_M: U5.AL7(IO_5A_AL7/DQ4R/DIFFIO_RX_R7N/DIFFOUT_R14N) ; also on sheet 3
Input5_P: U5.AK8(IO_5A_AK8/DQ4R/DIFFIO_RX_R7P/DIFFOUT_R14P) ; also on sheet 3
Input6_M: U5.AJ6(IO_5A_AJ6/DQSN3R/DIFFIO_RX_R5N/DIFFOUT_R10N) ; also on sheet 3
Input6_P: U5.AJ7(IO_5A_AJ7/DQS3R/DIFFIO_RX_R5P/DIFFOUT_R10P) ; also on sheet 3
Input7_M: U5.AH7(IO_5A_AH7/DQ2R/DIFFIO_RX_R4N/DIFFOUT_R8N) ; also on sheet 3
Input7_P: U5.AJ8(IO_5A_AJ8/DQ2R/DIFFIO_RX_R4P/DIFFOUT_R8P) ; also on sheet 3
Input8_M: U5.AH8(IO_5A_AH8/DQSN4R/DIFFIO_RX_R6N/DIFFOUT_R12N) ; also on sheet 3
Input8_P: U5.AJ9(IO_5A_AJ9/DQS4R/DIFFIO_RX_R6P/DIFFOUT_R12P) ; also on sheet 3
Input12_M: U5.L5(IO_6C_L5/DQSN9R/DIFFIO_RX_R18N/DIFFOUT_R35N) ; also on sheet 3
Input12_P: U5.K6(IO_6C_K6/DQS9R/DIFFIO_RX_R18P/DIFFOUT_R35P) ; also on sheet 3
Input13_M: U5.K5(IO_6C_K5/DQSN8R/DIFFIO_RX_R17N/DIFFOUT_R33N) ; also on sheet 3
Input13_P: U5.J5(IO_6C_J5/DQS8R/DIFFIO_RX_R17P/DIFFOUT_R33P) ; also on sheet 3
Input14_M: U5.H6(IO_6A_H6/DIFFIO_RX_R21N/DIFFOUT_R41N) ; also on sheet 3
Input14_P: U5.J7(IO_6A_J7/DIFFIO_RX_R21P/DIFFOUT_R41P) ; also on sheet 3
Input16_M: U5.L6(IO_6C_L6/DQ8R/DIFFIO_RX_R16N/DIFFOUT_R31N) ; also on sheet 3
Input16_P: U5.M7(IO_6C_M7/DQ8R/DIFFIO_RX_R16P/DIFFOUT_R31P) ; also on sheet 3
Input17_M: U5.K7(IO_6C_K7/DQSN10R/DIFFIO_RX_R20N/DIFFOUT_R39N) ; also on sheet 3
Input17_P: U5.L8(IO_6C_L8/DQS10R/DIFFIO_RX_R20P/DIFFOUT_R39P) ; also on sheet 3
Input19_M: U5.AG8(IO_5A_AG8/DIFFIO_RX_R8N/DIFFOUT_R16N) ; also on sheet 3
Input19_P: U5.AG9(IO_5A_AG9/DIFFIO_RX_R8P/DIFFOUT_R16P) ; also on sheet 3
Input20_M: U5.AG6(IO_5C_AG6/DQ5R/DIFFIO_RX_R10N/DIFFOUT_R20N) ; also on sheet 3
Input20_P: U5.AF6(IO_5C_AF6/DQ5R/DIFFIO_RX_R10P/DIFFOUT_R20P) ; also on sheet 3
Input21_M: U5.AE6(IO_5C_AE6/DQSN5R/DIFFIO_RX_R9N/DIFFOUT_R18N) ; also on sheet 3
Input21_P: U5.AF7(IO_5C_AF7/DQS5R/DIFFIO_RX_R9P/DIFFOUT_R18P) ; also on sheet 3
Input22_M: U5.AD6(IO_5C_AD6/DQSN6R/DIFFIO_RX_R11N/DIFFOUT_R22N) ; also on sheet 3
Input22_P: U5.AE7(IO_5C_AE7/DQS6R/DIFFIO_RX_R11P/DIFFOUT_R22P) ; also on sheet 3
Input23_M: U5.AD8(IO_5C_AD8/DQSN7R/DIFFIO_RX_R12N/DIFFOUT_R24N) ; also on sheet 3
Input23_P: U5.AD9(IO_5C_AD9/DQS7R/DIFFIO_RX_R12P/DIFFOUT_R24P) ; also on sheet 3
Input24_M: U5.AC7(IO_5C_AC7/DQ7R/DIFFIO_RX_R13N/DIFFOUT_R26N) ; also on sheet 3
Input24_P: U5.AB8(IO_5C_AB8/DQ7R/DIFFIO_RX_R13P/DIFFOUT_R26P) ; also on sheet 3
Input25_M: U5.M8(IO_6C_M8/DQ10R/DIFFIO_RX_R19N/DIFFOUT_R37N) ; also on sheet 3
Input25_P: U5.L9(IO_6C_L9/DQ10R/DIFFIO_RX_R19P/DIFFOUT_R37P) ; also on sheet 3
Input26_M: U5.H8(IO_6A_H8/DQSN11R/DIFFIO_RX_R23N/DIFFOUT_R45N) ; also on sheet 3
Input26_P: U5.G9(IO_6A_G9/DQS11R/DIFFIO_RX_R23P/DIFFOUT_R45P) ; also on sheet 3
Input29_M: U5.G8(IO_6A_G8/DQ11R/DIFFIO_RX_R22N/DIFFOUT_R43N) ; also on sheet 3
Input29_P: U5.F9(IO_6A_F9/DQ11R/DIFFIO_RX_R22P/DIFFOUT_R43P) ; also on sheet 3
Input30_M: U5.G6(IO_6A_G6/DQSN12R/DIFFIO_RX_R24N/DIFFOUT_R47N) ; also on sheet 3
Input30_P: U5.G7(IO_6A_G7/DQS12R/DIFFIO_RX_R24P/DIFFOUT_R47P) ; also on sheet 3
Input31_M: U5.F6(IO_6A_F6/DQ13R/DIFFIO_RX_R25N/DIFFOUT_R49N) ; also on sheet 3
Input31_P: U5.F7(IO_6A_F7/DQ13R/DIFFIO_RX_R25P/DIFFOUT_R49P) ; also on sheet 3
Input32_M: U5.E6(IO_6A_E6/DQSN14R/DIFFIO_RX_R27N/DIFFOUT_R53N) ; also on sheet 3
Input32_P: U5.D7(IO_6A_D7/DQS14R/DIFFIO_RX_R27P/DIFFOUT_R53P) ; also on sheet 3
Input33_M: U5.D6(RDN6A/DIFFIO_RX_R28N/DIFFOUT_R55N) ; also on sheet 3
Input33_P: U5.C7(RUP6A/DIFFIO_RX_R28P/DIFFOUT_R55P) ; also on sheet 3
Input34_M: U5.C5(IO_6A_C5/DQSN13R/DIFFIO_RX_R26N/DIFFOUT_R51N) ; also on sheet 3
Input34_P: U5.C6(IO_6A_C6/DQS13R/DIFFIO_RX_R26P/DIFFOUT_R51P) ; also on sheet 3
OSTROBE_N: U5.N11(IO_6A_N11/DIFFIO_TX_R28N/DIFFOUT_R56N) ; also on sheet 4
OSTROBE_P: U5.N12(IO_6A_N12/DIFFIO_TX_R28P/DIFFOUT_R56P) ; also on sheet 4
PG: R20.2 U7.9(PG)
PRESENT: U5.A9(IO_7A_A9/DQ2T/DIFFIO_RX_T3N/DIFFOUT_T6N) ; also on sheet 4
PUSHBUTTON1: U5.C23(IO_8A_C23/DQSN13T/DIFFIO_RX_T26N/DIFFOUT_T51N) ; also on sheet 2
PUSHBUTTON2: U5.C25(IO_8A_C25/DQSN15T/DIFFIO_RX_T29N/DIFFOUT_T57N) ; also on sheet 2
PUSHBUTTON3: U5.C26(IO_8A_C26/DQ16T/DIFFOUT_T60N) ; also on sheet 2
SPT1: U5.F25(IO_8A_F25/DQ15T/DIFFOUT_T56N) U16.14(B8)
TP_CMOS_1: TP29.1 U5.B6(IO_7A_B6/DQ1T/DIFFOUT_T3P)
TP_CMOS_2: TP28.1 U5.B8(IO_7A_B8/DQS2T/DIFFIO_RX_T2P/DIFFOUT_T4P)
TXEN: U5.A8(IO_7A_A8/DQSN2T/DIFFIO_RX_T2N/DIFFOUT_T4N) ; also on sheet 4
U13_BOOT: C86.1 U13.13(BOOT)
U13_EN: R43.2 R44.1 R123.1 U13.10(EN)
U13_VSENSE: R40.1 R42.1 U13.7(VSENSE)
USER_DIP0: U5.B23(IO_8A_B23/DQ12T/DIFFIO_RX_T24P/DIFFOUT_T47P) ; also on sheet 2
USER_DIP1: U5.B24(IO_8A_B24/DQS12T/DIFFIO_RX_T25P/DIFFOUT_T49P) ; also on sheet 2
USER_DIP2: U5.B26(IO_8A_B26/DQ16T/DIFFIO_RX_T30P/DIFFOUT_T59P) ; also on sheet 2
USER_DIP3: U5.B27(IO_8A_B27/DQS16T/DIFFIO_RX_T31P/DIFFOUT_T61P) ; also on sheet 2
USER_LED0: U5.A22(IO_8A_A22/DQ12T/DIFFOUT_T48P) ; also on sheet 2
USER_LED1: U5.A23(IO_8A_A23/DQ12T/DIFFIO_RX_T24N/DIFFOUT_T47N) ; also on sheet 2
USER_LED2: U5.A24(IO_8A_A24/DQSN12T/DIFFIO_RX_T25N/DIFFOUT_T49N) ; also on sheet 2
USER_LED3: U5.A25(IO_8A_A25/DQ16T/DIFFOUT_T60P) ; also on sheet 2
USER_LED4: U5.A26(IO_8A_A26/DQ16T/DIFFIO_RX_T30N/DIFFOUT_T59N) ; also on sheet 2
USER_LED5: U5.A27(IO_8A_A27/DQSN16T/DIFFIO_RX_T31N/DIFFOUT_T61N) ; also on sheet 2
USER_LED6: U5.A28(IO_8A_A28/DQ17T/DIFFOUT_T62P) ; also on sheet 2
USER_LED7: U5.A29(IO_8A_A29/DQ17T/DIFFOUT_T64P) ; also on sheet 2
N38636606: R23.2 U8.1(RT/CLK)
N38684744: C51.1 U8.13(BOOT)
N38692023: C51.2 L6.1 U8.11(PH1) U8.12(PH2)
N38717147: R29.2 R30.1 R117.1 U8.10(EN)
N38758692: C58.1 U8.9(SS/TR)
N38759863: C57.1 R27.1 U8.8(COMP)
N38796735: R24.1 R28.1 U8.7(VSENSE)
N39329231: R20.1 TP15.1(TP)
N39352684: R19.1 R21.1 U7.16(FB/SNS)
N39357177: C49.2 U7.15(SS)
N39394853: R22.2 R122.1 U7.11(EN)
N39486748: C60.2 U9.3(VREG5)
N39488974: R25.2 R26.1 U9.2(VFB)
N39500307: C61.2 U9.4(SS)
N39520363: C59.1 L7.1 U9.10(SW1) U9.11(SW2)
N39536131: C59.2 U9.12(VBST)
N39697235: C86.2 L10.1 U13.11(PH1) U13.12(PH2)
N39697276: C91.1 U13.9(SS/TR)
N39697334: C90.1 R41.1 U13.8(COMP)
N39697499: R39.2 U13.1(RT/CLK)
N39748772: C97.1 L11.1 U15.10(SW1) U15.11(SW2)
N39748780: R47.2 R48.1 U15.2(VFB)
N39748835: C97.2 U15.12(VBST)
N39748872: C98.2 U15.3(VREG5)
N39748888: C99.2 U15.4(SS)
N40105653: R32.1 R35.1 U10.7(VSENSE)
N40105663: C64.2 L8.1 U10.11(PH1) U10.12(PH2)
N40105684: R33.2 R36.1 R119.1 U10.10(EN)
N40105708: C70.1 U10.9(SS/TR)
N40105747: C69.1 R34.1 U10.8(COMP)
N40105844: C64.1 U10.13(BOOT)
N40105894: R31.2 U10.1(RT/CLK)
N40477874: C83.2 U12.3(VREG5)
N40477880: C82.1 L9.1 U12.10(SW1) U12.11(SW2)
N40477882: R37.2 R38.1 U12.2(VFB)
N40477947: C82.2 U12.12(VBST)
N40477997: C84.2 U12.4(SS)
N40549332: R118.1 R120.2 U11.7(S3) U11.9(S5)
N40558976: C74.1 R34.2
N45362819: R114.1 R115.1 U12.7(EN) U15.7(EN)
N45364246: R113.1 R121.1 U9.7(EN)
N45747552: R148.1 U20.10(FREQ)
N45747567: C295.1 U20.5(SS)
N45747801: R157.2 R158.1 U20.4(EN)
N45748163: D11.1 D11.2 L12.2 U20.1(SW1) U20.2(SW2)
N45748253: R145.2 R146.1 U20.9(FB)
N45846780: R147.1 U20.8(COMP)
N46019343: C89.1 J11.1(CENTER)
N46019345: C89.2 R78.2 R106.1 U22.1(1A)
N46019457: R161.1 U22.6(1Y)
N46019460: R161.2 U5.G20(IO_8A_G20/DIFFOUT_T46N)
N46019504: J14.1(CENTER) R107.1
N46041093: C76.2 C77.1 C78.1 C80.1 C81.1 F1.2 Q1.4(S4) Q1.7(S7) R162.2
N46041643: Q1.3(G3) U19.4(GATE)
N46057666: SJP1.2(Pin2) U23.5(DIR)
N46072692: SJP5.2(Pin2) U17.2(DIR)
N46072914: JP2.2(Pin2) U17.22(\\~{OE}\)
N46075799: SJP6.2(Pin2) U24.5(DIR)
N46075858: SJP4.2(Pin2) U16.2(DIR)
N46075905: JP3.2(Pin2) U16.22(\\~{OE}\)
N46091921: TP13.1 U16.10(A8)
N46106005: R107.2 U25.1(1A)
N46106015: R11.1 U25.6(1Y)
N46106758: J15.1(CENTER) R12.1
N46106973: R111.2 U26.1(1A)
N46106975: R13.1 U26.6(1Y)
N46107280: R14.1 U21.6(1Y)
N46109990: C63.1 R27.2
N46123383: R12.2 U25.3(2A)
N46123415: R108.1 U25.4(2Y)
N46123492: J16.1(CENTER) R111.1
N46123509: R112.2 U21.1(1A)
N46123519: J17.1(CENTER) R112.1
N46123655: R11.2 U5.G22(IO_8A_G22/DQ13T/DIFFOUT_T50N)
N46123664: R108.2 U5.G23(IO_8A_G23/DQ14T/DIFFOUT_T54P)
N46123673: R13.2 U5.G24(IO_8A_G24/DQ14T/DIFFOUT_T54N)
N46123684: R14.2 U5.G25(IO_8A_G25/DQ15T/DIFFOUT_T56P)
N46227347: C93.1 R41.2
N46227348: D12.1(ANODE) R162.1

Not connected (* = marked no-connect by the designer): D14 2*; U5 AC18(IO_3C_AC18/PLL_B1_CLKOUT4/DIFFOUT_B27N)* AD18(IO_3C_AD18/PLL_B1_CLKOUT3/DIFFOUT_B27P)* AE18(IO_3C_AE18/PLL_B1_CLKOUT0P/DIFFOUT_B29P)* AE19(IO_3C_AE19/DIFFIO_RX_B14P/DIFFOUT_B28P)* AF18(IO_3C_AF18/PLL_B1_CLKOUT0N/DIFFOUT_B29N)* AF19(IO_3C_AF19/DIFFIO_RX_B14N/DIFFOUT_B28N)* AF20(IO_3A_AF20/DIFFOUT_B19P)* AF21(IO_3A_AF21/DIFFIO_RX_B10P/DIFFOUT_B20P)* AG21(IO_3A_AG21/DIFFIO_RX_B10N/DIFFOUT_B20N)* AH20(IO_3A_AH20/DIFFOUT_B19N)* AH25(IO_3A_AH25/DQ3B/DIFFOUT_B9P)* AJ13(IO_4A_AJ13/DQ14B/DIFFIO_RX_B27N/DIFFOUT_B53N)* AJ21(IO_3A_AJ21/DQ5B/DIFFOUT_B13P)* AM8(IO_4A_AM8/DQ16B/DIFFOUT_B60P)* AN14(IO_4C_AN14/DQ11B/DIFFOUT_B44P)* AN26(IO_3A_AN26/DQ2B/DIFFIO_RX_B3P/DIFFOUT_B6P)* H9(IO_6A_H9/DQ11R/DIFFIO_TX_R22P/DIFFOUT_R44P) H11(IO_6A_H11/DQ12R/DIFFIO_TX_R23P/DIFFOUT_R46P) J8(IO_6A_J8/DQ11R/DIFFIO_TX_R22N/DIFFOUT_R44N) J9(IO_6A_J9/DQ13R/DIFFIO_TX_R25P/DIFFOUT_R50P) J10(IO_6A_J10/DQ12R/DIFFIO_TX_R23N/DIFFOUT_R46N) K8(IO_6A_K8/DQ13R/DIFFIO_TX_R25N/DIFFOUT_R50N) K10(IO_6A_K10/DQ14R/DIFFIO_TX_R26N/DIFFOUT_R52N) K11(IO_6A_K11/DQ14R/DIFFIO_TX_R26P/DIFFOUT_R52P) M11(IO_6A_M11/DQ14R/DIFFIO_TX_R27N/DIFFOUT_R54N) M12(IO_6A_M12/DQ14R/DIFFIO_TX_R27P/DIFFOUT_R54P) N10(IO_6C_N10/DIFFIO_TX_R20P/DIFFOUT_R40P) P9(IO_6C_P9/DIFFIO_TX_R20N/DIFFOUT_R40N) P11(IO_6A_P11/DQ12R/DIFFIO_TX_R24N/DIFFOUT_R48N) P12(IO_6A_P12/DQ12R/DIFFIO_TX_R24P/DIFFOUT_R48P) R12(IO_6C_R12/DQ9R/DIFFIO_TX_R18N/DIFFOUT_R36N) R13(IO_6C_R13/DQ9R/DIFFIO_TX_R18P/DIFFOUT_R36P); U8 14(PWRGD)*; U9 6(PG)*; U10 14(PWRGD)*; U12 6(PG)*; U13 14(PWRGD)*; U15 6(PG)*; U17 10(A8)* 14(B8)*; U19 1(NC1)* 3(NC3)*; U21 3(2A)* 4(2Y)*; U22 3(2A)* 4(2Y)*; U26 4(2Y)*

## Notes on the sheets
sheet 10
- BANK3
- 1.8V
sheet 11
- BANK4
- 1.8V
sheet 12
- BANK5
- 2.5V
sheet 13
- BANK6
- 2.5V
sheet 14
- BANK7
- 3.0V
sheet 15
- 3.0V
- BANK8
- PLACE CLOSE
- TO FPGA
sheet 16
- 0.9V, 1.1V, 1.5V, 1.8V
- 0.9V FPGA
- 1.1V
- 1.5V
- 0.9V DDR
- 1.8V
sheet 17
- 5V DC
  INPUT
- 3.0V
- 2.5V, 3.0V, 3.3V, 5V
- 3.3V
- 2.5V
